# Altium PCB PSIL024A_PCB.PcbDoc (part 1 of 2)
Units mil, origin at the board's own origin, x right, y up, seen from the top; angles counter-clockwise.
Board outline 5700 x 3550 mil, 4 copper layers (Top Layer, MidLayer1, MidLayer2, Bottom Layer), stack 61.2 mil thick; 205 components, 107 nets, 481 pads, 240 vias.
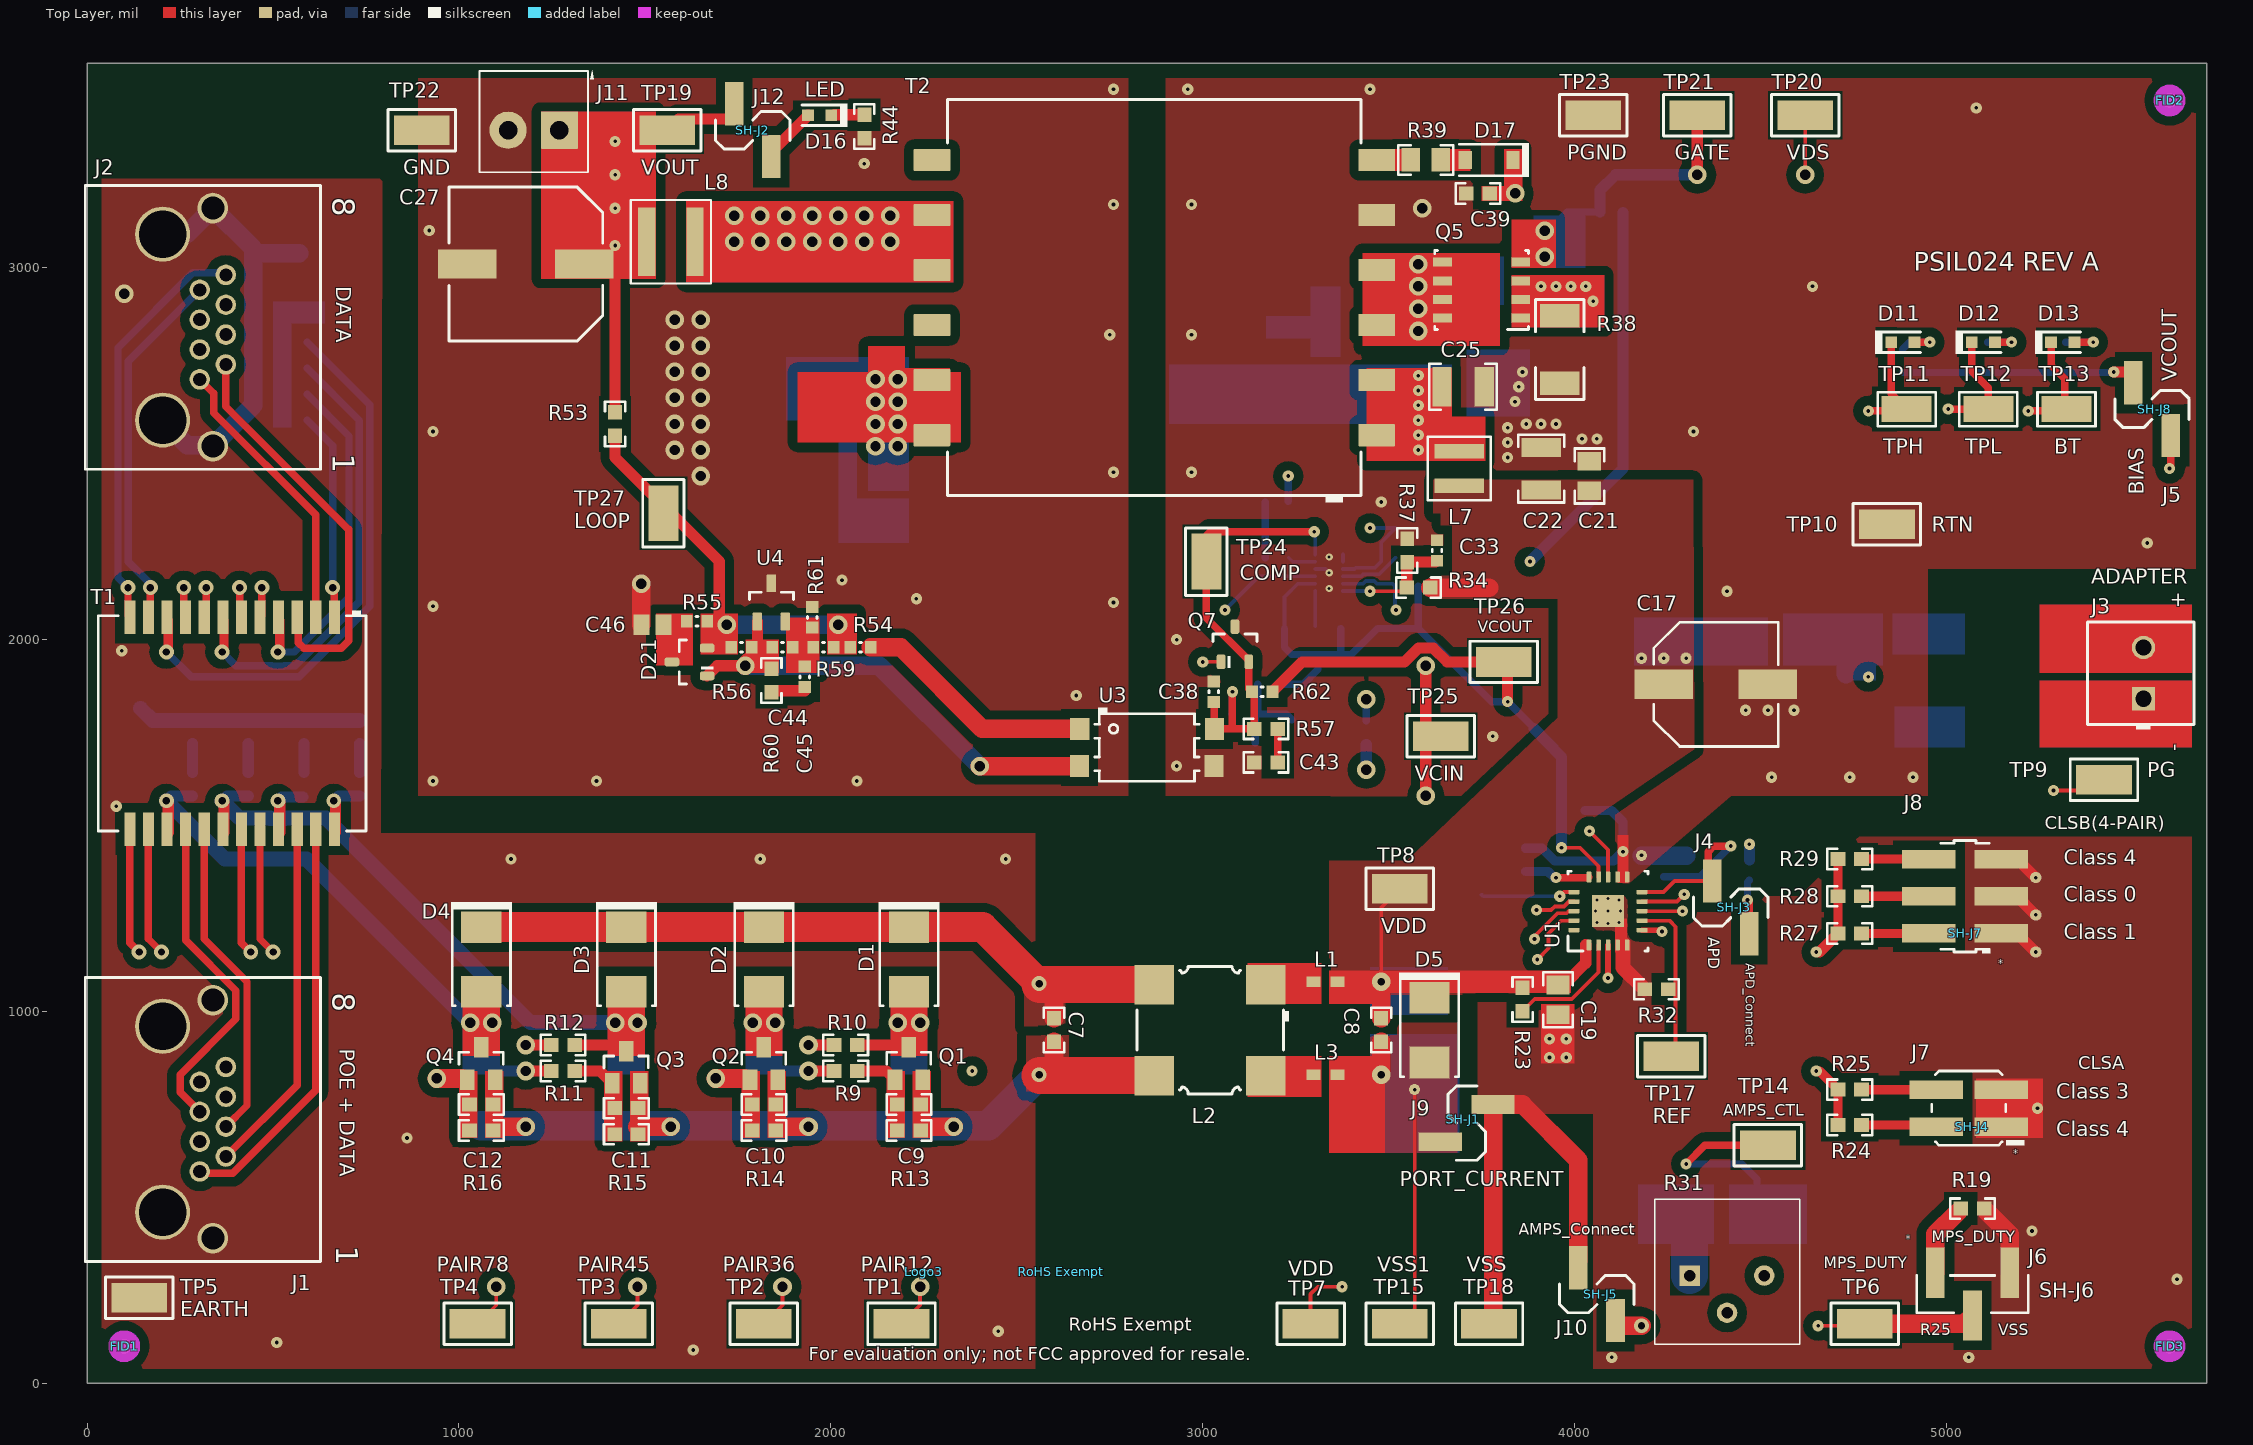
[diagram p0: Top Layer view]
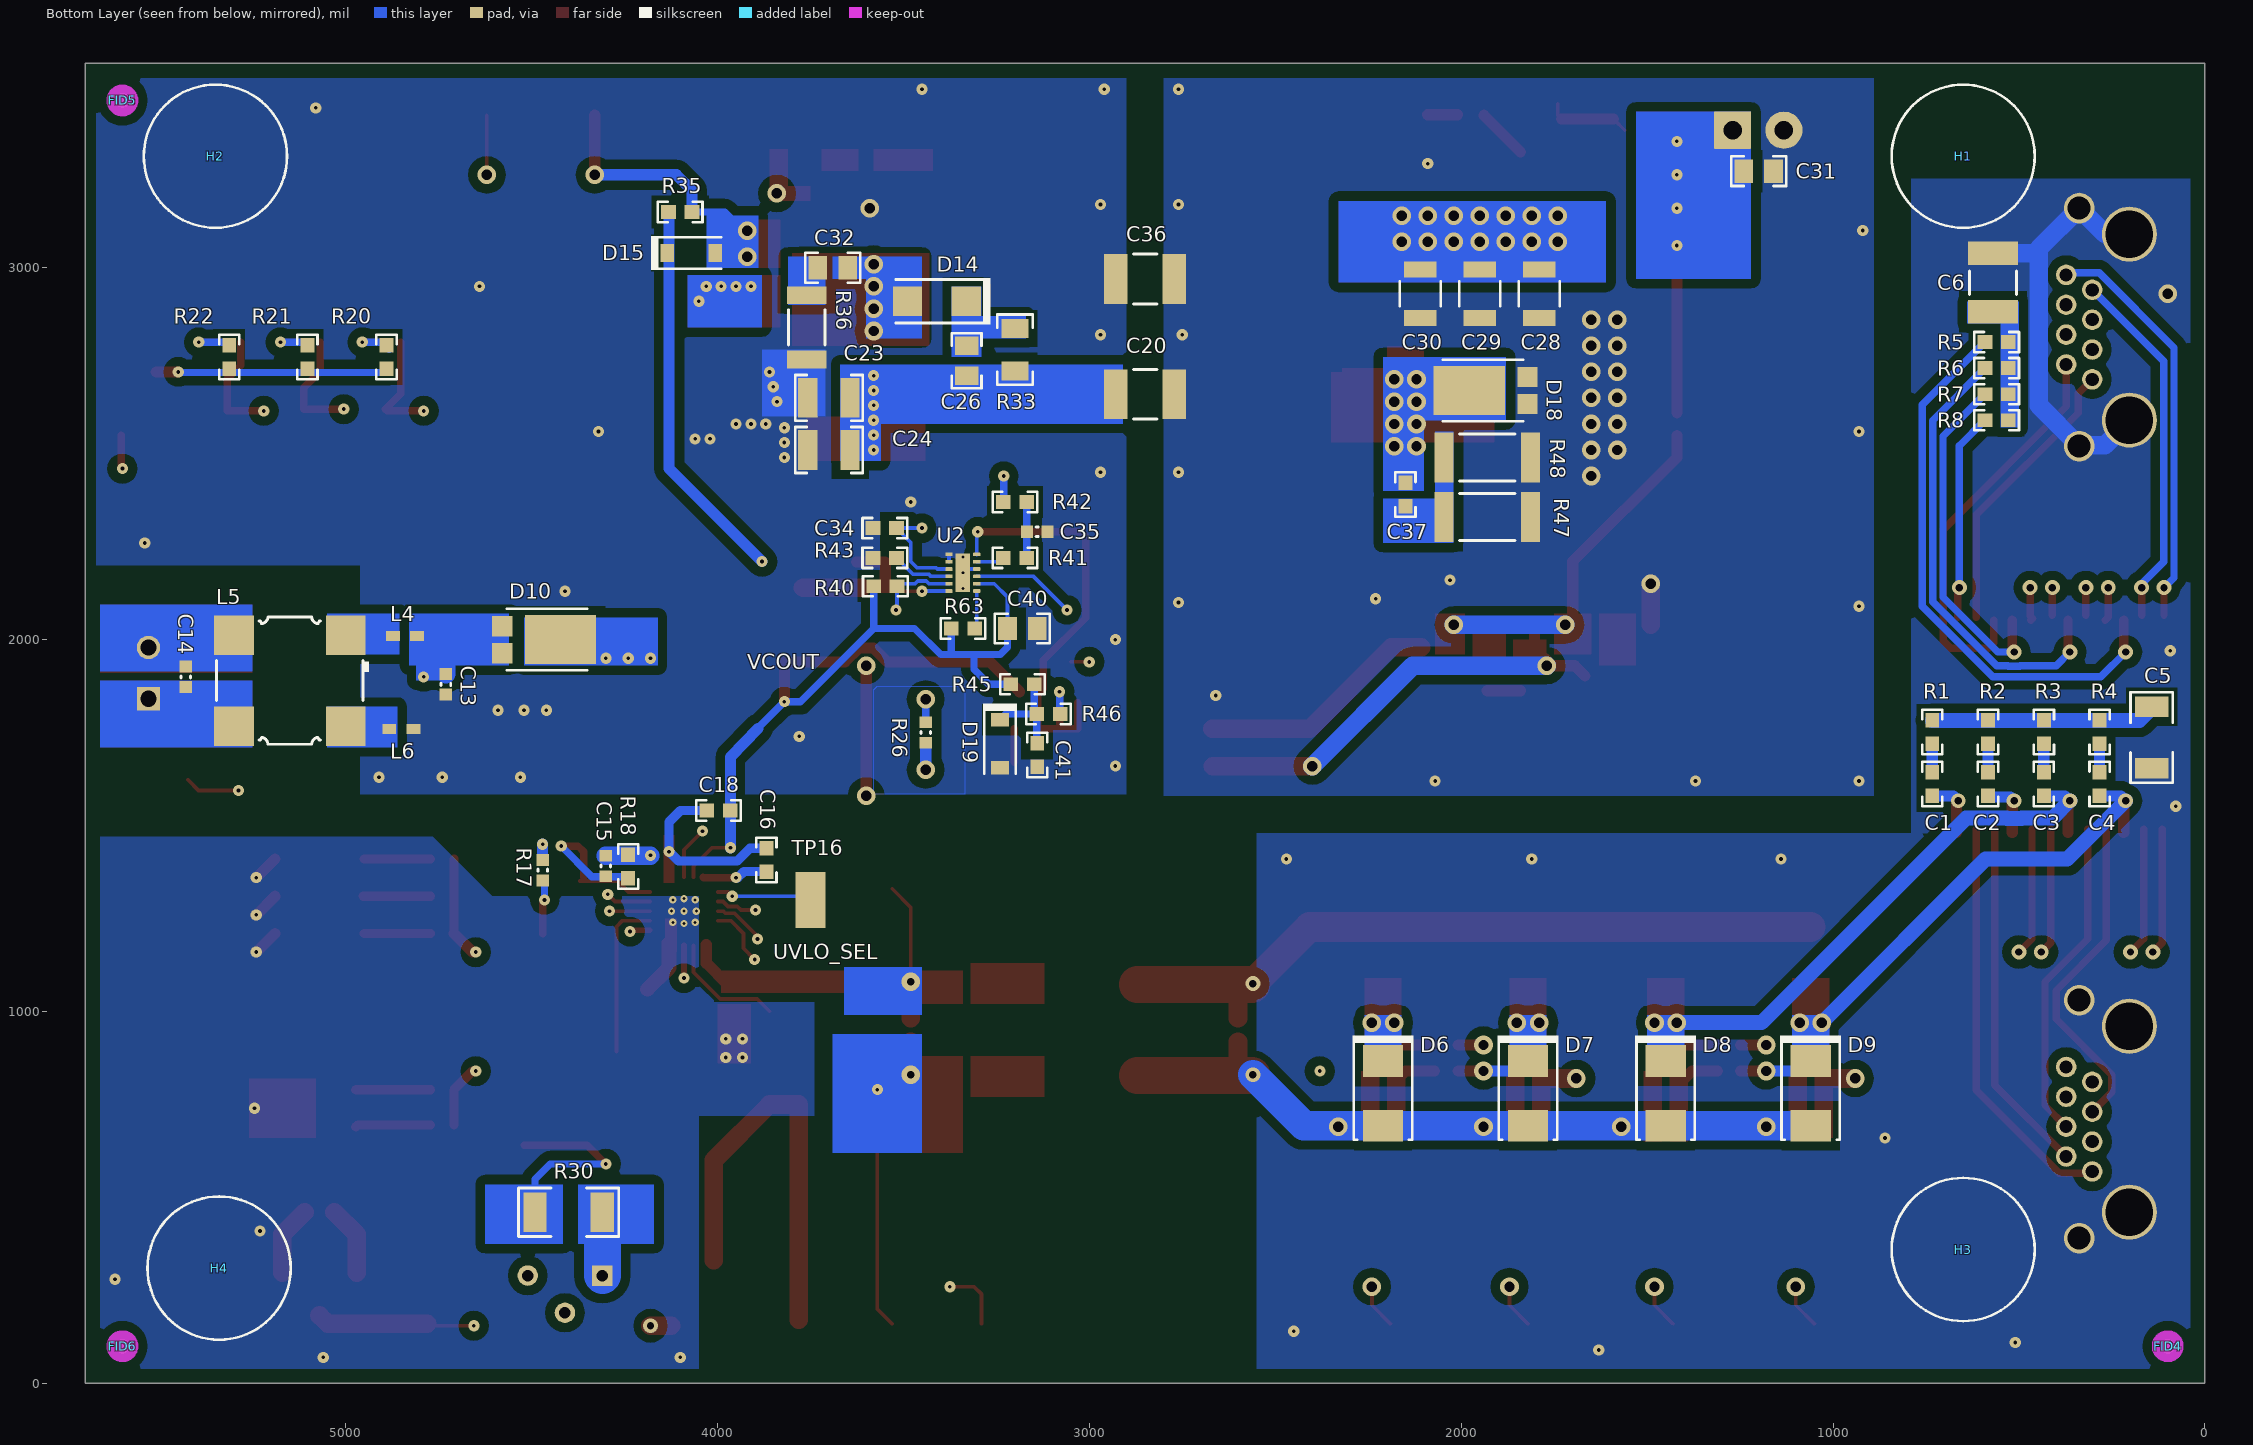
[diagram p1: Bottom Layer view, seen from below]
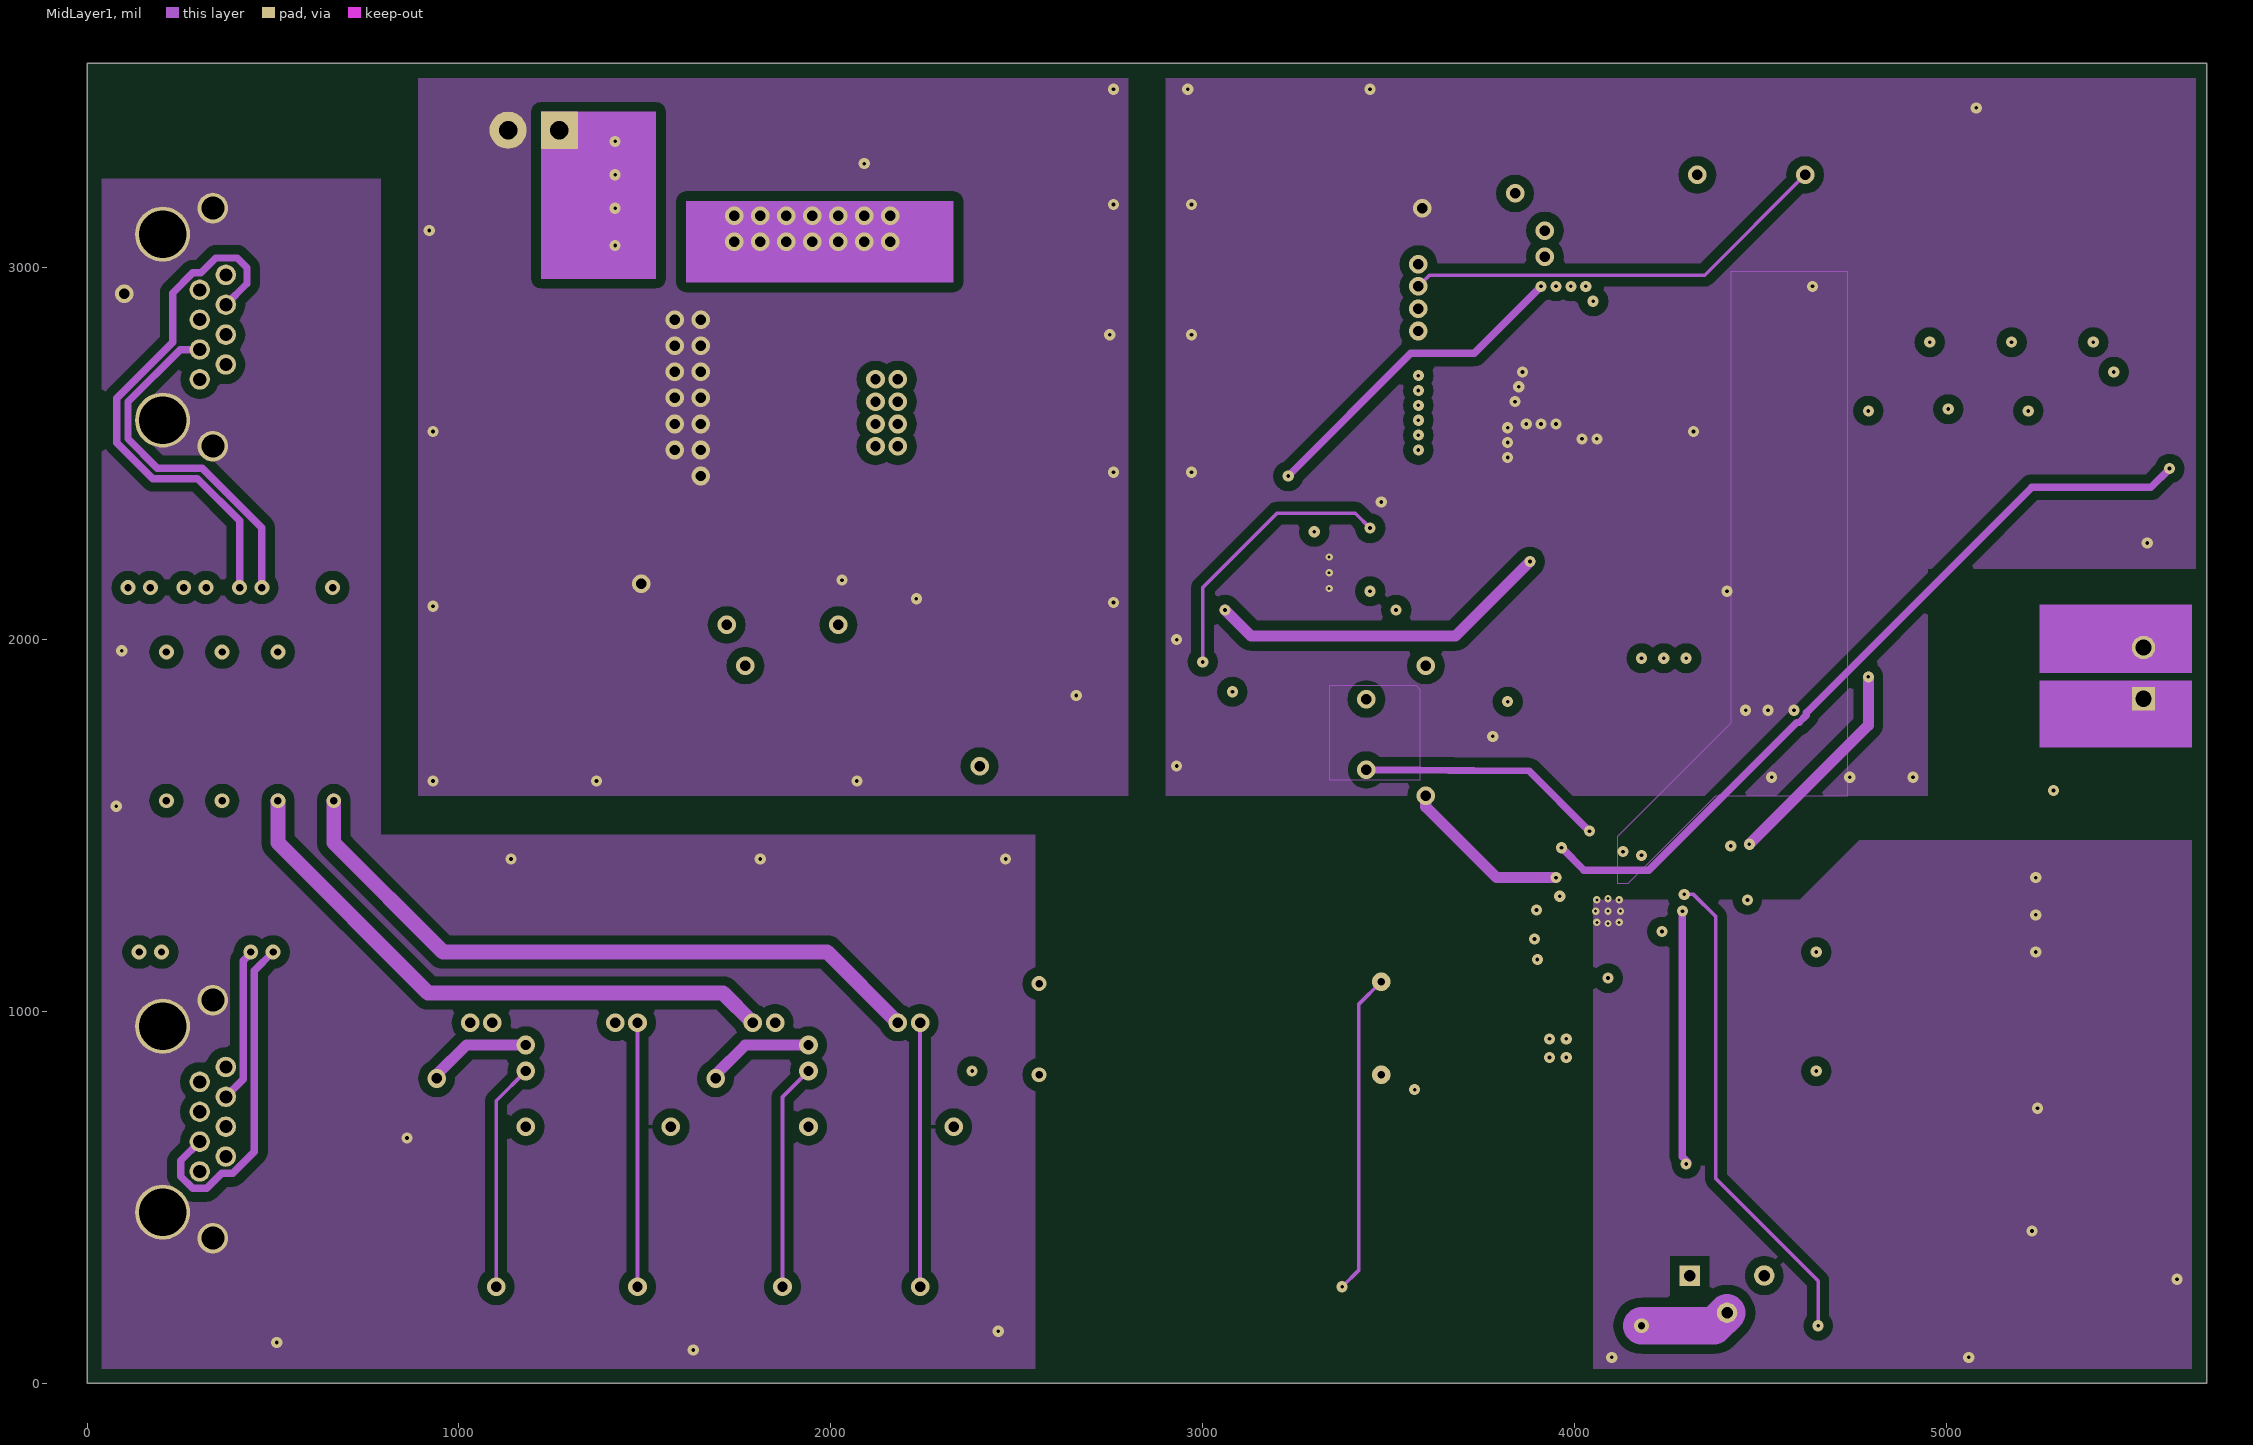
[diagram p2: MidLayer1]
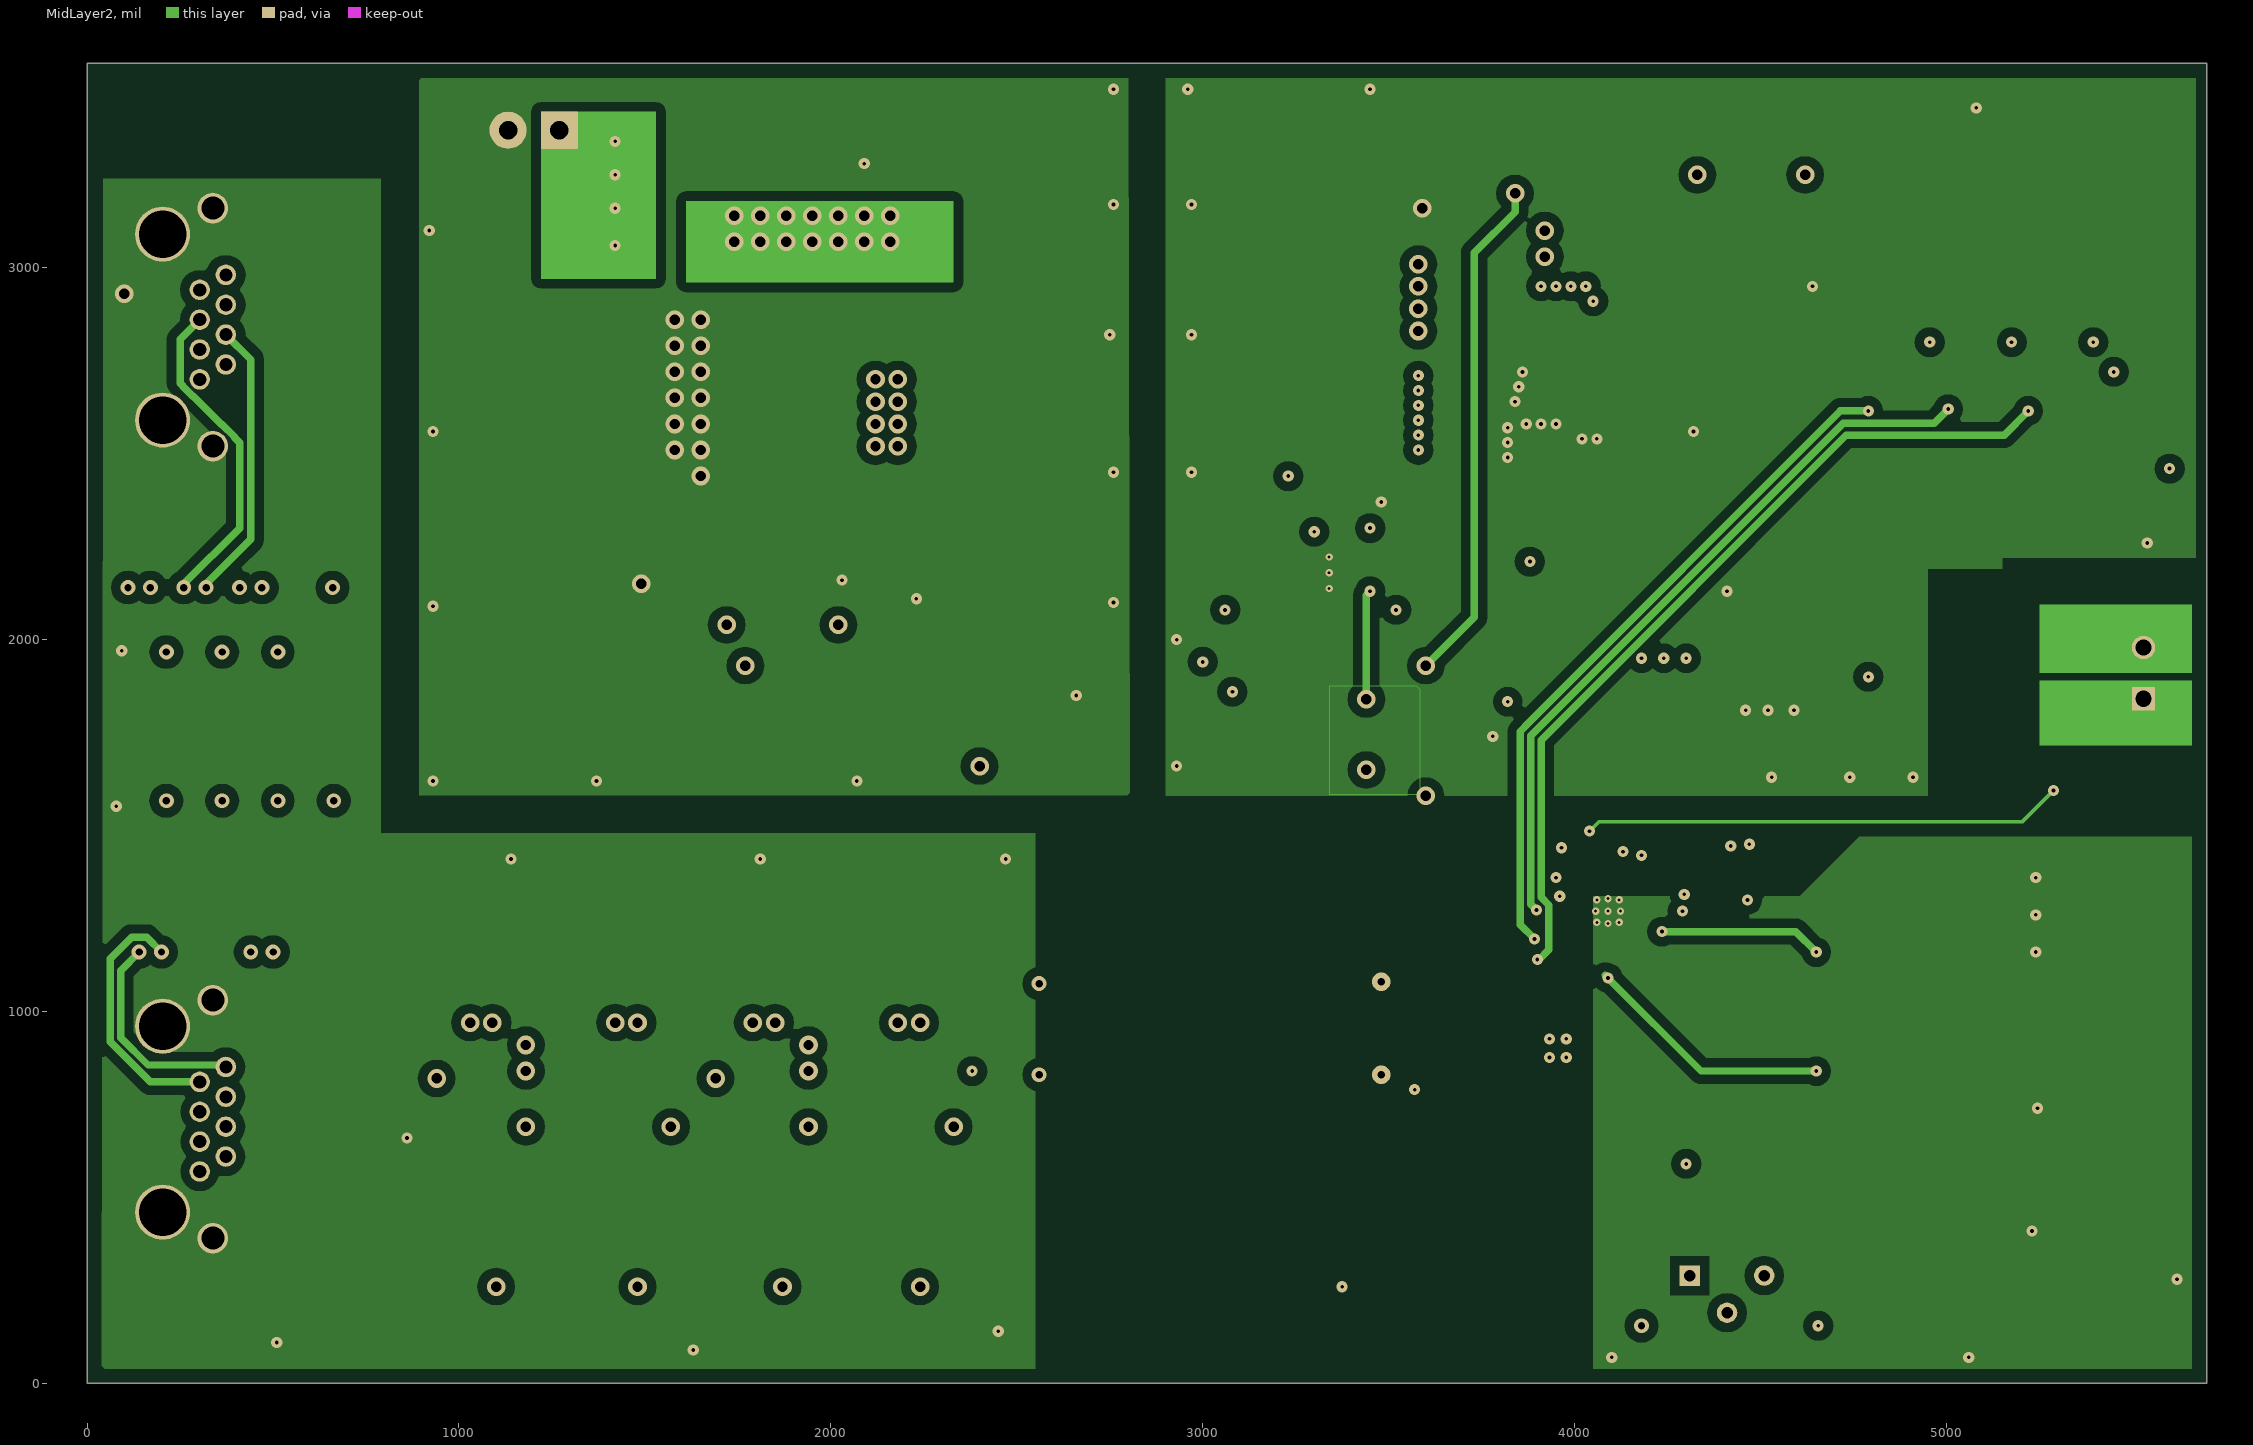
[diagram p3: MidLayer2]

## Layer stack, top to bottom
Top Solder: solder mask 0.4, Solder Resist, Dk 3.5
Top Layer: signal copper 2.8
Dielectric1: core 14.2, FR-4, Dk 4.8
MidLayer1: signal copper 2.8
Dielectric2: prepreg 21.6, FR-4, Dk 4.8
MidLayer2: signal copper 2.8
Dielectric3: core 14.2, FR-4, Dk 4.8
Bottom Layer: signal copper 2.8
Bottom Solder: solder mask 0.4, Solder Resist, Dk 3.5

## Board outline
0,0 5700,0 5700,3550 0,3550

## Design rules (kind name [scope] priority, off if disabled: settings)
AcuteAngle [All] p1: minimum=4.50000000000000E+0001 checktracksonly=TRUE
AssemblyTestPointUsage [All] p1: valid=2
BoardOutlineClearance BoardOutlineClearance_MountingHoles [OnCopper and InComponentClass('Mounting Holes')] p1: gap=40
BoardOutlineClearance BoardOutlineClearance_Poly [OnCopper and InPoly] p2: gap=25
BoardOutlineClearance [OnCopper and Not InComponentClass('Logo') and not InComponentClass('FiducialMark') and not InRegion(1000,500,4000,800)] p3: gap=20
Clearance Clearance_Keepouts [((IsTrack Or IsArc) And Not InPoly) And IsFree and IsKeepOut vs ((IsTrack Or IsArc) And Not InPoly) And IsFree and IsKeepOut] p1: gap=0
Clearance Clearance_Poly [InPolygon] p2: gap=25
Clearance [All] p3: gap=7.87
ComponentClearance ComponentClearance_MountingHoles_FiducialMarks [InComponentClass('Mounting Holes') vs InComponentClass('FiducialMark')] p1: gap=50 collisioncheckmode=3 verticalgap=10 showdistances=FALSE
ComponentClearance ComponentClearance_Shunt [InComponentClass('Header') vs InComponentClass('Shunt')] p2: gap=0 collisioncheckmode=3 verticalgap=0 showdistances=FALSE
ComponentClearance ComponentClearance_Logo [InComponentClass('Logo')] p3: gap=50 collisioncheckmode=3 verticalgap=10 showdistances=FALSE
ComponentClearance ComponentClearance_ScrewToNut [(HasFootprint('NY PMS 440 0025 PH')) vs (HasFootprint('Keystone_1902C'))] p4: gap=5 collisioncheckmode=3 verticalgap=10 showdistances=FALSE
ComponentClearance ComponentClearance_MountingHoles [InComponentClass('Mounting Holes')] p5: gap=250 collisioncheckmode=3 verticalgap=100000 showdistances=FALSE
ComponentClearance ComponentClearance_SmallPassives [HasFootprint('0201*') or HasFootprint('0402*') or HasFootprint('0508') or HasFootprint('0603*') or HasFootprint('0612') or HasFootprint('0805*') or HasFootprint('0815*') or HasFootprint('0830*') or HasFootprint('1206*') or HasFootprint('1210*') or HasFootprint('1808*') or HasFootprint('1812*') or HasFootprint('1825*') or HasFootprint('2010*') or HasFootprint('2220*') or HasFootprint('2225*') or HasFootprint('2512*') or HasFootprint('2728*') or HasFootprint('3518*') vs HasFootprint('0201*') or HasFootprint('0402*') or HasFootprint('0508') or HasFootprint('0603*') or HasFootprint('0612') or HasFootprint('0805*') or HasFootprint('0815*') or HasFootprint('0830*') or HasFootprint('1206*') or HasFootprint('1210*') or HasFootprint('1808*') or HasFootprint('1812*') or HasFootprint('1825*') or HasFootprint('2010*') or HasFootprint('2220*') or HasFootprint('2225*') or HasFootprint('2512*') or HasFootprint('2728*') or HasFootprint('3518*')] p6: gap=14.96 collisioncheckmode=3 verticalgap=10 showdistances=FALSE
ComponentClearance ComponentClearance_THtoSMT [IsThruComponent vs IsSMTComponent] p7: gap=40 collisioncheckmode=3 verticalgap=30 showdistances=FALSE
ComponentClearance ComponentClearance_THtoTH [IsThruComponent vs IsThruComponent] p8: gap=30 collisioncheckmode=3 verticalgap=30 showdistances=FALSE
ComponentClearance [All] p9: gap=30 collisioncheckmode=3 verticalgap=10 showdistances=FALSE
DiffPairsRouting [All] p1: maxlimit=100 minlimit=10 mostfreqgap=10 toplayer_minwidth=15 toplayer_maxwidth=15 toplayer_prefwidth=15 midlayer1_minwidth=15 midlayer1_maxwidth=15 midlayer1_prefwidth=15 midlayer2_minwidth=15 midlayer2_maxwidth=15 midlayer2_prefwidth=15 bottomlayer_minwidth=15 bottomlayer_maxwidth=15 bottomlayer_prefwidth=15 maxuncoupledlength=1000
FabricationTestPointUsage TestPointUsage [All] p1: valid=2 allowmultiple=FALSE
FabricationTestpoint Testpoint [All] p1: side=3 testpointundercomponent=TRUE minsize=40 maxsize=100 preferedsize=60 minholesize=0 maxholesize=40 preferedholesize=32 testpointgrid=1 allowsidetop=TRUE allowsidebottom=TRUE usegrid=TRUE gridtolerance=0.01
FanoutControl Fanout_LCC [IsLCC] p1: bgadir=Out bgaviamode=Centered fanoutstyle=Auto fanoutdirection=Alternating viagrid=1 // Fanout_LCC (Default Rule)
FanoutControl Fanout_BGA [IsBGA] p2: bgadir=Out bgaviamode=Centered fanoutstyle=Auto fanoutdirection=Alternating viagrid=1 // Fanout_BGA (Default Rule)
FanoutControl Fanout_Default [All] p4: bgadir=Out bgaviamode=Centered fanoutstyle=Auto fanoutdirection=Alternating viagrid=1 // Fanout_Default (Default Rule)
FanoutControl Fanout_Small [(CompPinCount < 5)] p5: bgadir=Out bgaviamode=Centered fanoutstyle=Auto fanoutdirection=OutThenIn viagrid=1 // Fanout_Small (Default Rule)
HoleSize [All] p1: absolutevalues=TRUE maxlimit=251 minlimit=7.87 maxpercent=80.000 minpercent=20.000
MinimumAnnularRing MinimumAnnularRing_ThermalPadVias [IsVia and InAnyComponent] p1: minimumring=5.91
MinimumAnnularRing [All] p2: minimumring=5
MinimumSolderMaskSliver MinimumSolderMaskSliver_Logo [InComponentClass('Logo') vs InComponentClass('Logo')] p1: minsoldermaskwidth=0.7
MinimumSolderMaskSliver [All] p2: minsoldermaskwidth=3.94
PlaneConnect [All] p1: planeconnectstyle=Direct reliefexpansion=10 reliefentries=4 reliefconductorwidth=10 reliefairgap=10
PolygonConnect [All] p1: connectstyle=Direct reliefconductorwidth=10 reliefentries=4 polygonreliefangle="90 Angle" airgapwidth=10
RoutingVias ThermalPadVias [IsVia and InAnyComponent] p1: holewidth=7.87 width=19.68 viastyle="Through Hole" minholewidth=7.87 minwidth=19.68 maxholewidth=12.99 maxwidth=23.62
RoutingVias [All] p2: holewidth=16 width=34 viastyle="Through Hole" minholewidth=7.87 minwidth=20 maxholewidth=40 maxwidth=65
SilkToBoardRegionClearance [Not ((IsComment or IsDesignator) And (Hide <> 'False')) and not InRegion(1000,500,4000,800)] p1:
SilkToSilkClearance SilkToSilkClearance_Pb-FreeLogo [(HasFootprint('Pb-Free_Overlay_Medium') OR HasFootprint('Pb-Free_Overlay_Small')) vs (HasFootprint('Pb-Free_Overlay_Medium') OR HasFootprint('Pb-Free_Overlay_Small'))] p1: silktosilkclearance=0
SilkToSilkClearance [All] p2: silktosilkclearance=4
SilkToSolderMaskClearance SilkToComponentPadClearance [IsPad and InAnycomponent] p1: minsilkscreentomaskgap=5 clearancetoexposedcopper=TRUE
SilkToSolderMaskClearance "Silk to Solder Mask Opening" [All] p2: minsilkscreentomaskgap=4 clearancetoexposedcopper=FALSE
SolderMaskExpansion [All] p1: expansion=1.97
Width [All] p1: maxlimit=100 minlimit=6 preferedwidth=10 checkconnectedcopper=TRUE
15 further rules are at their usual default settings.

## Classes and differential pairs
component class PSIL024A_sch2: C13 C14 C15 C16 C17 C18 C19 D10 D11 D12 D13 J3 J4 J5 J6 J7 J8 J9 J10 L4 L5 L6 R17 R18 R19 R20 R21 R22 R23 R24 R25 R26 R27 R28 R29 R30 R31 R32 TP6 TP7 TP8 TP9 TP10 TP11 TP12 TP13 TP14 TP15 TP16 TP17 TP18 U1
component class Shunt: SH-J1 SH-J2 SH-J3 SH-J4 SH-J5 SH-J6 SH-J7 SH-J8
component class PSIL024A_sch3: C20 C21 C22 C23 C24 C25 C26 C27 C28 C29 C30 C31 C32 C33 C34 C35 C36 C37 C38 C39 C40 C41 C43 C44 C45 C46 D14 D15 D16 D17 D18 D19 D21 J11 J12 L7 L8 L? Q5 Q7 R33 R34 R35 R36 R37 R38 R39 R40 R41 R42 R43 R44 R45 R46 R47 R48 R53 R54 R55 R56 R57 R59 R60 R61 R62 R63 T2 TP19 TP20 TP21 TP22 TP23 TP24 TP25 TP26 TP27 U2 U3 U4
component class PSIL024A_sch1: C1 C2 C3 C4 C5 C6 C7 C8 C9 C10 C11 C12 D1 D2 D3 D4 D5 D6 D7 D8 D9 J1 J2 L1 L2 L3 Q1 Q2 Q3 Q4 R1 R2 R3 R4 R5 R6 R7 R8 R9 R10 R11 R12 R13 R14 R15 R16 T1 TP1 TP2 TP3 TP4 TP5
component class Header: J4 J5 J6 J7 J8 J9 J10 J12
component class AssemblyNote: ZZ1 ZZ2 ZZ3
component class FiducialMark: FID1 FID2 FID3 FID4 FID5 FID6
component class PSIL024A_EVM_Hardware: FID1 FID2 FID3 FID4 FID5 FID6 H1 H2 H3 H4 Logo3 "RoHS Exempt" SH-J1 SH-J2 SH-J3 SH-J4 SH-J5 SH-J6 SH-J7 SH-J8 ZZ1 ZZ2 ZZ3

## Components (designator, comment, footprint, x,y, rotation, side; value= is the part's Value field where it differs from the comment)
C1 "C1608X7R2A103K" 0603 733.15,1611.5 r90 bottom
C2 "C1608X7R2A103K" 0603 583.15,1611.5 r90 bottom
C3 "C1608X7R2A103K" 0603 433.15,1611.5 r90 bottom
C4 "C1608X7R2A103K" 0603 283.15,1611.5 r90 bottom
C5 "GR442QR73D102KW01L" 1808 143.15,1736.85 r270 bottom
C6 "1812GC102KAT1A" 1812_220 570,2960 r90 bottom
C7 "C1608X7R2A102K" 0603 2600,950 r270 top
C8 "C1608X7R2A102K" 0603 3480,950 r270 top
C9 "885012006060" 0603 2210,750 r0 top
C10 "885012006060" 0603 1820,750 r0 top
C11 "885012006060" 0603 1450,740 r0 top
C12 "885012006060" 0603 1060,750 r0 top
C13 "C1608X7R2A102K" 0603L 4730,1880 r270 bottom
C14 "C1608X7R2A102K" 0603L 5430,1900 r270 bottom
C15 "C1608X7R1H103K" 0603L 4300,1391.3 r270 bottom
C16 "GRM188R61H103KA01D" 0603 3868.25,1407.75 r90 bottom
C17 "EEE-FK1J470P" SM_RADIAL_F 4380,1880 r0 top
C18 "06033D104KAT2A" 0603 3996.75,1540.5 r0 bottom
C19 "C0805C104K1RACTU" 0805_HV 3955.5,1031.25 r270 top
C20 "1812GC472KAT1A" 1812_254 2850,2660 r0 bottom
C21 "C2012X7R2A104K125AA" 0805_HV 4040,2440 r270 top
C22 "GRM32ER72A225KA35L" 1210_270 3910,2460 r90 top
C23 "GRM32ER72A225KA35L" 1210_270 3700,2650 r0 bottom
C24 "GRM32ER72A225KA35L" 1210_270 3700,2510 r0 bottom
C25 "GRM32ER72A225KA35L" 1210_270 3700,2680 r0 top
C26 "C2012X7R2A104K125AA" 0805_HV 3330,2750 r270 bottom
C27 "PCV1E271MCL1GS" PCV_1000x1270 1180,3010 r180 top
C28 "C1210C106K3RACTU" 1210_280 1790,2930 r270 bottom
C29 "C1210C106K3RACTU" 1210_280 2110,2930 r270 bottom
C30 "C1210C106K3RACTU" 1210_280 1950,2930 r270 bottom
C31 "GRM21BR71E105KA99L" 0805_HV 1200,3260 r180 bottom
C32 "GRM21A5C2E101JW01D" 0805_HV 3690,3000 r0 bottom
C33 "C0603C221J5GACTU" 0603L 3630,2240 r90 top
C34 "C0603C223K3RACTU" 0603 3550,2300 r0 bottom
C35 "GRM1885C1H101JA01D" 0603L 3140,2290 r180 bottom
C36 "1812GC472KAT1A" 1812_254 2850,2970 r0 bottom
C37 "001" 0603 2150,2390 r270 bottom
C38 "GRM1885C1H392JA01D" 0603L 3030,1860 r90 top
C39 "06033C104JAT2A" 0603 3740,3200 r180 top
C40 "GRM21BR71E105KA99L" 0805_HV 3180,2030 r180 bottom
C41 "EMK107BB7225KA-T" 0603 3140,1690 r270 bottom
C43 "06033C473JAT2A" 0603 3170,1670 r180 top
C44 "GRM1885C1H101JA01D" 0603L 1870,1980 r180 top
C45 "C1608X7R1H473K080AA" 0603L 1930,1900 r270 top
C46 "GRM21BR71E105KA99L" 0805L 1520,2040 r180 top
D1 "B2100-13-F" SMB 2210,1140 r270 top
D2 "B2100-13-F" SMB 1820,1140 r270 top
D3 "B2100-13-F" SMB 1450,1140 r270 top
D4 "B2100-13-F" SMB 1060,1140 r270 top
D5 "SMBJ58A-13-F" SMB 3610,950 r270 top
D6 "DNP" SMB 2210,780 r270 bottom
D7 "DNP" SMB 1820,780 r270 bottom
D8 "DNP" SMB 1450,780 r270 bottom
D9 "DNP" SMB 1060,780 r270 bottom
D10 "100V" PowerDI5 4500,2000 r180 bottom
D11 "Yellow" WL-SMCW_YELLOW 4882.8,2799.98 r0 top
D12 "Yellow" WL-SMCW_YELLOW 5099.36,2799.98 r0 top
D13 "Yellow" WL-SMCW_YELLOW 5312.8,2799.98 r0 top
D14 "ES2DA-13-F" SMA 3410,2910 r0 bottom
D15 "MMSD4148T1G" SOD-123 4070,3040 r180 bottom
D16 "150060YS75000" WL-SMCW_YELLOW 1970,3410 r180 top
D17 "MMSD4148T1G" SOD-123 3770,3290 r180 top
D18 "001" PowerDI5 1900,2670 r0 bottom
D19 "MMSZ5231B-7-F" SOD-123 3240,1720 r270 bottom
D21 "BAT54S-7-F" SOT-23 1620,1940 r180 top
FID1 "Fiducial" Fiducial10-20 100,100 r0 top
FID2 "Fiducial" Fiducial10-20 5600,3450 r0 top
FID3 "Fiducial" Fiducial10-20 5600,100 r0 top
FID4 "Fiducial" Fiducial10-20 100,100 r180 bottom
FID5 "Fiducial" Fiducial10-20 5600,3450 r180 bottom
FID6 "Fiducial" Fiducial10-20 5600,100 r180 bottom
H1 "SJ61A2" Bumpon_SJ61A2 650,3300 r180 bottom locked
H2 "SJ61A2" Bumpon_SJ61A2 5350,3300 r180 bottom locked
H3 "SJ61A2" Bumpon_SJ61A2 650,360 r180 bottom locked
H4 "SJ61A2" Bumpon_SJ61A2 5340,310 r180 bottom locked
J1 "1-406541-1" TEC_1-406541-1 310,710 r270 top
J2 "1-406541-1" TEC_1-406541-1 310,2840 r270 top
J3 "39357-0002" Molex_39357-0002 5530,1910 r90 top
J4 "87898-0204" Molex_87898-0204 4420,1280 r180 top
J5 "87898-0204" Molex_87898-0204 5552.8,2620 r180 top
J6 "TSM-103-01-L-SV" Samtec_TSM-103-01-X-SV 5070,240 r0 top
J7 "15-91-2040" Molex_15-91-2040 5060,740 r90 top
J8 "TSM-103-01-L-DV" Samtec_TSM-103-01-x-DV 5050,1310 r180 top
J9 "Port Current" Molex_87898-0204 3710,700 r270 top
J10 "AMPS_Connect" Molex_87898-0204 4060,240 r0 top
J11 "ED555/2DS" TERM_BLK_ED555-2DS 1270,3370 r180 top
J12 "LED" Molex_87898-0204 1790,3370 r0 top
L1 "" WE-CBF_0603 3330,1080 r0 top
L2 "744272251" WE-SL5 3020,950 r270 top
L3 "" WE-CBF_0603 3330,830 r0 top
L4 "" WE-CBF_0603 4840,2010 r180 bottom
L5 "744272251" WE-SL5 5150,1890 r270 bottom
L6 "" WE-CBF_0603 4850,1760 r180 bottom
L7 "XFL4020-332MEB" XFL4020 3690,2460 r90 top
L8 "XAL5030-161MEB" XAL5030 1570,3070 r180 top
Logo3 "FCC disclaimer" FCC_disclaimer 2250,300 r0 top
Q1 "FDN8601" SSOT-3 2210,860 r0 top
Q2 "FDN8601" SSOT-3 1820,860 r0 top
Q3 "FDN8601" SSOT-3 1450,850 r0 top
Q4 "FDN8601" SSOT-3 1060,860 r0 top
Q5 "FDMS86252" TRANS_Fairchild_PQFN08A 3750,2940 r180 top
Q7 "FMMT718TA" SOT-23 3086.69,1987.71 r90 top
R1 "CRCW060375R0FKEA" 0603 733.15,1751.5 r270 bottom
R2 "CRCW060375R0FKEA" 0603 583.15,1751.5 r270 bottom
R3 "CRCW060375R0FKEA" 0603 433.15,1751.5 r270 bottom
R4 "CRCW060375R0FKEA" 0603 283.15,1751.5 r270 bottom
R5 "CRCW060375R0FKEA" 0603 560,2800 r180 bottom
R6 "CRCW060375R0FKEA" 0603 560,2730 r180 bottom
R7 "CRCW060375R0FKEA" 0603 560,2660 r180 bottom
R8 "CRCW060375R0FKEA" 0603 560,2590 r180 bottom
R9 "CRCW06031M00FKEA" 0603 2040,840 r180 top
R10 "CRCW06031M00FKEA" 0603 2040,910 r0 top
R11 "CRCW06031M00FKEA" 0603 1280,840 r180 top
R12 "CRCW06031M00FKEA" 0603 1280,910 r0 top
R13 "CRCW0603232KFKEA" 0603 2210,680 r180 top
R14 "CRCW0603232KFKEA" 0603 1820,680 r180 top
R15 "CRCW0603232KFKEA" 0603 1450,670 r180 top
R16 "CRCW0603232KFKEA" 0603 1060,680 r180 top
R17 "CRCW0603237KFKEA" 0603L 4470,1380 r90 bottom
R18 "CRCW06039K53FKEA" 0603 4240,1390 r270 bottom
R19 "CRCW060360K4FKEA" 0603 5070,470 r0 top
R20 "CRCW060324K9FKEA" 0603 4890,2760 r270 bottom
R21 "CRCW060324K9FKEA" 0603 5102.8,2759.98 r270 bottom
R22 "CRCW060324K9FKEA" 0603 5312.8,2759.98 r270 bottom
R23 "RC0603FR-0727K4L" 0603 3860.25,1032.5 r90 top
R24 "CRCW060363R4FKEA" 0603 4740,695 r180 top
R25 "CRCW060390R9FKEA" 0603 4740,790 r180 top
R26 "CRCW06030000Z0EA" 0603L 3440,1750 r90 bottom
R27 "CRCW0603249RFKEA" 0603 4740,1210 r180 top
R28 "CRCW06031K21FKEA" 0603 4740,1310 r180 top
R29 "CRCW060363R4FKEA" 0603 4740,1410 r180 top
R30 "CRCW20101K00FKEF" 2010 4400,460 r0 bottom
R31 "3386P-1-202LF" BOURNS_3386P 4410,300 r0 top
R32 "CRCW060349K9FKEA" 0603 4220,1060 r180 top
R33 "CRCW120639K0JNEA" 1206 3200,2780 r270 bottom
R34 "133k" 0603 3580,2140 r0 top
R35 "CRCW060310R0JNEA" 0603 4100,3150 r180 bottom
R36 "CRCW201075R0JNEF" 2010L 3760,2840 r90 bottom
R37 "RT0603DRE074K99L" 0603 3550,2240 r270 top
R38 "CSRN2010FK20L0" 2010 3960,2780 r90 top
R39 "CRCW08055R23FKEA" 0805_HV 3600,3290 r180 top
R40 "100k" 0603 3548.46,2143.7 r180 bottom
R41 "MCR03EZPJ000" 0603 3200,2220 r180 bottom
R42 "499" 0603 3200,2370 r0 bottom
R43 "71.5k" 0603 3550,2220 r180 bottom
R44 "CRCW06034K42FKEA" 0603 2090,3380 r90 top
R45 "CRCW06032K61FKEA" 0603 3180,1880 r0 bottom
R46 "CRCW06032K32FKEA" 0603 3110,1800 r0 bottom
R47 "001" 2512 1930,2330 r0 bottom
R48 "001" 2512 1930,2490 r0 bottom
R53 "CRCW060350R0FKEA" 0603 1420,2580 r90 top
R54 "CRCW06032K10FKEA" 0603L 2080,1980 r180 top
R55 "CRCW060310K0FKEA" 0603L 1640,2050 r0 top
R56 "CRCW06034K99FKEA" 0603L 1760,1980 r180 top
R57 "CRCW0603887RFKEA" 0603 3170,1760 r180 top
R59 "CRCW060310K0FKEA" 0603L 1980,1980 r0 top
R60 "CRCW060314K7FKEA" 0603 1840,1890 r270 top
R61 "CRCW06032K61FKEA" 0603L 1950,2060 r270 top
R62 "CRCW060310K2FKEA" 0603L 3160,1860 r0 top
R63 "MCR03EZPJ000" 0603 3340,2030 r180 bottom
"RoHS Exempt" "EU RoHS Exempt Logo" EURoHS_Exempt_60mil 2620,300 r90 top
SH-J1 "SPC02SYAN" SPC02SYAN 3700,710 r270 top
SH-J2 "SPC02SYAN" SPC02SYAN 1790,3370 r0 top
SH-J3 "SPC02SYAN" SPC02SYAN 4430,1280 r0 top
SH-J4 "SPC02SYAN" SPC02SYAN 5070,690 r0 top
SH-J5 "SPC02SYAN" SPC02SYAN 4070,240 r0 top
SH-J6 "SPC02SYAN" SPC02SYAN 5000,250 r180 top
SH-J7 "SPC02SYAN" SPC02SYAN 5050,1210 r0 top
SH-J8 "SPC02SYAN" SPC02SYAN 5560,2620 r0 top
T1 "7490220122" Wurth_7490220122 390,1775 r270 top
T2 "750317065" Wurth_EFD25_4476 2870,2920 r180 top
TP1 "TESTPOINT" Keystone_5019 2190,160 r0 top
TP2 "TESTPOINT" Keystone_5019 1820,160 r0 top
TP3 "TESTPOINT" Keystone_5019 1430,160 r0 top
TP4 "TESTPOINT" Keystone_5019 1050,160 r0 top
TP5 "TESTPOINT" Keystone_5019 140,230 r0 top
TP6 "TESTPOINT" Keystone_5019 4780,160 r0 top
TP7 "VDD" Keystone_5019 3290,160 r0 top
TP8 "VDD" Keystone_5019 3530,1330 r0 top
TP9 "PG" Keystone_5019 5423.75,1623 r0 top
TP10 "RTN" Keystone_5019 4840,2310 r0 top
TP11 "5015" Testpoint_Keystone_Miniature 4892.8,2619.98 r0 top
TP12 "5015" Testpoint_Keystone_Miniature 5112.8,2619.98 r0 top
TP13 "5015" Testpoint_Keystone_Miniature 5322.8,2619.98 r0 top
TP14 "AMPS_CTL" Keystone_5019 4520,640 r0 top
TP15 "VSS1" Keystone_5019 3530,160 r0 top
TP16 "UVLO_SEL" Keystone_5019 3750,1300 r90 bottom
TP17 "REF" Keystone_5019 4260,880 r180 top
TP18 "VSS" Keystone_5019 3770,160 r0 top
TP19 "VOUT" Keystone_5019 1560,3370 r0 top
TP20 "TESTPOINT" Keystone_5019 4620,3410 r0 top
TP21 "TESTPOINT" Keystone_5019 4330,3410 r0 top
TP22 "TESTPOINT" Keystone_5019 900,3370 r180 top
TP23 "TESTPOINT" Keystone_5019 4050,3410 r0 top
TP24 "COMP" Keystone_5019 3010,2210 r90 top
TP25 "TESTPOINT" Keystone_5019 3640,1740 r0 top
TP26 "VCOUT" Keystone_5019 3810,1940 r0 top
TP27 "TESTPOINT" Keystone_5019 1550,2340 r90 top
U1 "TPS2373-3RGWR" RGW0020B 4090,1270 r90 top
U2 "LM51551QDSSRQ1" DSS0012C 3340,2180 r0 bottom
U3 "FOD817AS" N04C 2850,1710 r0 top
U4 "TL431LIAIDBZR" DBZ0003A_M 1840,2100 r90 top
ZZ1 "These assemblies are ESD sensitive, ESD precautions shall be observed." AssemblyNote 115,4529.11 r0 top
ZZ2 "These assemblies must be clean and free from flux and all contaminants. Use of no clean flux is not acceptable." AssemblyNote 115,4440.56 r0 top
ZZ3 "These assemblies must comply with workmanship standards IPC-A-610 Class 2, unless otherwise specified." AssemblyNote 115,4352 r0 top

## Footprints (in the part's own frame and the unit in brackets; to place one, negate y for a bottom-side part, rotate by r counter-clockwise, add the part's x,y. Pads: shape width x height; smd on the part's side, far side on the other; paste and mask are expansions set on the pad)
0603 [mm] "0603 from SM-752 data"
  rect 1x0.95 smd: 1(-0.8,0) 2(0.8,0)
  silkscreen extent -1.52,-0.69 1.52,0.69, body extent -0.87,-0.47 0.87,0.47, height 1
0603L [mm] "0603 from SM-752 data"
  rect 0.8x0.85 smd: 1(-0.7,0) 2(0.7,0)
  silkscreen extent -0.07,-0.33 0.07,0.33, body extent -0.87,-0.47 0.87,0.47, height 1
0805_HV [mil] "0805 with 30mil clearance between pads"
  rect 50x63 smd: 1(-40,0) 2(40,0)
  silkscreen extent -74,-40 74,40, body extent -43,-29 43,29, height 57
0805L [mm] "0805 from SM-752 data"
  rect 1.1x1.4 smd: 1(-0.75,0) 2(0.75,0)
  body extent -1.1,-0.72 1.1,0.72, height 1.45
1206 [mm] "1206 from SM-752 data"
  rect 1.3x1.85 smd: 1(-1.45,0) 2(1.45,0)
  silkscreen extent -2.4,-1.21 2.4,1.21, body extent -1.7,-0.9 1.7,0.9, height 1.35
1210_270 [mm] "1210"
  rect 1.3x2.7 smd: 1(-1.45,0) 2(1.45,0)
  silkscreen extent -2.32,-1.57 2.32,1.57, body extent -1.7,-1.35 1.7,1.35, height 2.7
1210_280 [mm] "SMD, 2-Leads, Body 3.6x2.8mm, Height 2.8mm"
  rect 1.1x2.2 smd: 1(-1.65,0) 2(1.65,0)
  silkscreen extent -0.84,-1.4 0.84,1.4, body extent -1.8,-1.4 1.8,1.4, height 2.8
1808 [mm] "Chip Capacitor, Body 4.6x2.0mm, IPC Medium Density"
  rect 1.4x2.3 smd: 1(-2.1,0) 2(2.1,0)
  silkscreen extent -3.1,-1.45 3.1,1.45, body extent -2.47,-1.2 2.47,1.2, height 2.03
1812_220 [mm] "1812"
  rect 1.6x3.4 smd: 1(-2,0) 2(2,0)
  silkscreen extent -0.8,-1.6 0.8,1.6, body extent -2.4,-1.7 2.4,1.7, height 2.2
1812_254 [mm] "SMD, 2-Leads, Body 4.8x3.4mm"
  rect 1.6x3.4 smd: 1(-2,0) 2(2,0)
  silkscreen extent -0.8,-1.7 0.8,1.7, body extent -2.4,-1.7 2.4,1.7, height 2.54
2010 [mm] "Chip Capacitor, Body 5.08x2.54mm, IPC Medium Density"
  rect 1.6x2.7 smd: 1(-2.3,0) 2(2.3,0)
  silkscreen extent -3.42,-1.65 3.42,1.65, body extent -2.73,-1.45 2.73,1.45, height 1.66
2010L [mm]
  rect 1.2x2.7 smd: 1(-2.2,0) 2(2.2,0)
  silkscreen extent -1.2,-1.25 1.2,1.25, body extent -2.73,-1.45 2.73,1.45, height 1.66
2512 [mm] "Chip Resistor, Body 6.3x3.2mm, IPC Medium Density"
  rect 1.3x3.4 smd: 1(-2.95,0) 2(2.95,0)
  silkscreen extent -1.9,-1.6 1.9,1.6, body extent -3.22,-1.67 3.22,1.67, height 0.71
AssemblyNote [mil] "Assembly Note"
BOURNS_3386P [mil] "BOURND"
  rect 55x55 hole 31: 1(-100,-10)
  round 55 hole 31: 2(0,-110) 3(100,-10)
  silkscreen extent -195,-195 195,195, body extent -193,-192 193,193, height 201
Bumpon_SJ61A2 [mil] "3M Hemispherical Bumpon transparent"
  round 1 on Mech4: 0(0,0)
  silkscreen extent -192,-192 192,192, body extent -193,-192 193,192, height 250
DBZ0003A_M [mm] "SOT23, 3-Leads, Body 2.9x1.3mm, Pitch 0.95mm, Lead Span 2.4mm, IPC Low Density"
  rrect15% 1.2x0.65 smd: 1(-1.3,0.95) 2(-1.3,-0.95) 3(1.3,0)
  silkscreen extent 0.2,-1.5 0.7,1.5, body extent -1.26,-1.46 1.26,1.46, height 0.98
DSS0012C [mm] "WSON-12"
  rrect40% 0.5x0.25 smd: 1(-0.95,1.25) 2(-0.95,0.75) 3(-0.95,0.25) 4(-0.95,-0.25) 5(-0.95,-0.75) 6(-0.95,-1.25) 7(0.95,-1.25) 8(0.95,-0.75) 9(0.95,-0.25) 10(0.95,0.25) 11(0.95,0.75) 12(0.95,1.25)
  rrect11% 0.95x1.17 on Bottom Paste: 13(0,-0.685) 13(0,0.685)
  rrect11% 1x2.65 smd paste-0.5: 13(0,0)
  body extent -1,-1.5 1,1.5, height 0.81
EURoHS_Exempt_60mil [mil] "EU RoHS Exempt symbol"
FCC_disclaimer [mil]
Fiducial10-20 [mm]
  round 1 smd mask+0.5: 1(0,0)
  Top Layer keep-out circle w1.178: c0,0 r0.5
Keystone_5019 [mm] "Test Point, Miniature, SMT"
  rect 3.8x2.03 smd: 1(0,0)
  silkscreen extent -2.31,-1.42 2.31,1.42, body extent -1.9,-1.02 1.9,1.02, height 2.29
Molex_15-91-2040 [mil] "Molex"
  rect 50x144.88 smd: 1(-50,-87.5) 2(-50,87.5) 3(50,-87.5) 4(50,87.5)
  silkscreen extent -100,-150 100,100, body extent -100,-137 100,138, height 380
Molex_39357-0002 [mm] "Terminal Block, 3.5 mm, 2x1, TH"
  rect 1.6x1.6 hole 1.1: 1(-1.75,0)
  round 1.6 hole 1.1: 2(1.75,0)
  silkscreen extent -3.86,-3.45 3.5,3.84, body extent -3.55,-3.45 3.56,3.84, height 8.51
Molex_87898-0204 [mm] "Header, 2.54 mm, 2x1, R/A, SMT"
  rect 1.27x2.96 smd: 1(-1.27,1.8) 2(1.27,-1.8)
  silkscreen extent -2.54,-1.27 2.54,1.27, body extent -2.54,-2.4 2.54,2.4, height 9.65
N04C [mm] "FAIRCHILD"
  rect 1.3x1.5 smd mask+0.065: 1(-4.587,1.27) 2(-4.612,-1.27) 3(4.588,-1.27) 4(4.613,1.27)
  silkscreen extent -3.56,-2.3 3.56,2.72, body extent -5.08,-2.3 5.08,2.3, height 3.87
PCV_1000x1270 [mm] "SMD, 2-Leads, Dia 10mm"
  rect 4x2 smd: 1(-4,0) 2(4,0)
  silkscreen extent -5.25,-5.25 5.25,5.25, body extent -5.25,-5.25 5.25,5.25, height 12.71
PowerDI5 [mm] "Diodes Inc recommended land pattern, ap02001.pdf rev 60"
  rect 1.4x1.39 smd: 1(-1.991,0.92) 2(-1.991,-0.92)
  rect 4.86x3.36 smd: 3(1.991,0)
  silkscreen extent -1.7,-2.1 3.8,2.1, body extent -2.27,-2.02 4.33,2.03, height 1.17
RGW0020B [mm] "QFN, 20-Leads, Body 5x5mm, Pitch 0.65mm, Thermal Pad 2.2x2.2mm, TI Recommended"
  rrect32% 0.75x0.31 smd: 1(-2.325,1.3) 2(-2.325,0.65) 3(-2.325,0) 4(-2.325,-0.65) 5(-2.325,-1.3) 11(2.325,-1.3) 12(2.325,-0.65) 13(2.325,0) 14(2.325,0.65) 15(2.325,1.3)
  rrect32% 0.31x0.75 smd: 6(-1.3,-2.325) 7(-0.65,-2.325) 8(0,-2.325) 9(0.65,-2.325) 10(1.3,-2.325) 16(1.3,2.325) 17(0.65,2.325) 18(0,2.325) 19(-0.65,2.325) 20(-1.3,2.325)
  rrect10% 0.98x0.98 on Top Paste: 21(-0.59,-0.59) 21(-0.59,0.59) 21(0.59,-0.59) 21(0.59,0.59)
  rrect5% 2.2x2.2 smd paste-1.1: 21(0,0)
  silkscreen extent -2.73,-2.73 2.73,2.73, body extent -2.5,-2.5 2.5,2.5, height 0.97
Samtec_TSM-103-01-x-DV [mm] "Header, 2.54mm, 3x2, SMT"
  rect 3.68x1.27 smd: 1(-2.475,2.54) 2(2.475,2.54) 3(-2.475,0) 4(2.475,0) 5(-2.475,-2.54) 6(2.475,-2.54)
  silkscreen extent -1.75,-3.81 1.65,3.9, body extent -3.85,-3.81 3.85,3.81, height 9.65
Samtec_TSM-103-01-X-SV [mil] "Samtec recommended land pattern"
  rect 50x135 smd: 1(-100,57.5) 2(0,-57.5) 3(100,57.5)
  silkscreen extent -150,-50 150,50, body extent -150,-104 150,104, height 381
SM_RADIAL_F [mm] "8 x 10.2mm:  Panasonic F"
  rect 4x2 smd: 1(-3.55,0) 2(3.55,0)
  silkscreen extent -4.25,-4.25 4.25,4.25, body extent -4.25,-4.25 4.25,4.25, height 10.5
SMA [mm] "Molded Diode, 2-Leads, Body 4.3x2.6mm, IPC Medium Density, based on OnSemi component dimensions and land pattern"
  rect 2x2 smd: 1(-2,0) 2(2,0)
  silkscreen extent -3.66,-1.57 2.79,1.57, body extent -2.6,-1.3 2.6,1.3, height 2.42
SMB [mil] "Molded Diode, 2-Leads, Body 5.4x3.6mm, IPC Medium Density, based on OnSemi component dimensions"
  rect 85x107.99 smd: 1(-87.01,0) 2(87.01,0)
  silkscreen extent -155,-82 125,82, body extent -106,-71 106,71, height 91
SOD-123 [mm] "On Semi recommended land pattern"
  rect 0.915x1.22 smd: 1(-1.637,0) 2(1.637,0)
  silkscreen extent -2.74,-1.17 2.03,1.17, body extent -1.93,-0.9 1.93,0.9, height 1.35
SOT-23 [mm] "SOT23, 3-Leads, Body 2.9x1.3mm, Pitch 0.95mm, Lead Span 2.5mm, IPC Medium Density"
  rrect50% 1x0.6 smd: 1(-1.2,0.95) 2(-1.2,-0.95) 3(1.2,0)
  silkscreen extent -1.62,-1.5 0.7,1.5, body extent -1.16,-1.45 1.21,1.45, height 1
SPC02SYAN [mil] "SULLINS"
  round 1 on Mech3: 0(0,0)
  body extent -98,-47 99,47, height 366
SSOT-3 [mm] "SuperSOT-3"
  rect 1x1.4 smd: 1(-0.95,-1.1) 2(0.95,-1.1) 3(0,1.1)
  silkscreen extent -1.53,-0.05 1.5,0.77, body extent -1.52,-0.76 1.52,0.76, height 1.12
TEC_1-406541-1 [mm] "TE Connectivity"
  round 1.4 hole 0.89: 1(3.56,-0.18) 2(2.54,1.6) 3(1.52,-0.18) 4(0.5,1.6) 5(-0.52,-0.18) 6(-1.54,1.6) 7(-2.56,-0.18) 8(-3.58,1.6)
  round 2.1 hole 1.57: 9(8.12,0.71) 10(-8.14,0.71)
  round 3.759 hole 3.251: 11(6.34,-2.72) 12(-6.36,-2.72)
  silkscreen extent -9.69,-8 9.69,8.06, body extent -9.33,-8 9.31,7.75, height 14.8
TERM_BLK_ED555-2DS [mil]
  rrect4% 100x100 hole 50: 1(0,0)
  round 100 hole 50: 2(138,0)
  silkscreen extent -93,-161 215,113, body extent -69,-150 207,106, height 323
Testpoint_Keystone_Miniature [mil] "Miniature SMT test point"
  rect 135x70 smd: 1(0,0)
  silkscreen extent -78,-46 78,45, body extent -52,-20 52,20, height 61
TRANS_Fairchild_PQFN08A [mm] "Fairchild PQFN08A recommended land pattern"
  rect 1.27x0.61 smd: 1(-2.67,1.905) 2(-2.67,0.635) 3(-2.67,-0.635) 4(-2.67,-1.905) 5(2.67,-1.905) 6(2.67,-0.635) 7(2.67,0.635) 8(2.67,1.905)
  Top Layer region: -1.215,-2.55 2.535,-2.55 2.535,2.55 -1.215,2.55
  silkscreen extent -3.2,-2.7 3.2,2.7, body extent -3.05,-2.55 3.05,2.55, height 1.11
WE-CBF_0603 [mm] "WE_SMT-0603"
  rect 0.95x0.7 smd: 1(-0.825,0) 2(0.825,0)
  body extent -0.9,-0.5 0.9,0.5, height 1
WE-SL5 [mm] "SMD, 4-Leads, Body 8.7x10mm"
  rect 2.7x2.7 smd: 1(-3.11,3.81) 2(-3.11,-3.81) 3(3.11,-3.81) 4(3.11,3.81)
  silkscreen extent -4.35,-5 4.35,5.4, body extent -4.35,-5 4.35,5, height 6
WL-SMCW_YELLOW [mm] "WURTH"
  rect 0.8x0.8 smd: 1(-0.8,0) 2(0.8,0)
  silkscreen extent -1.9,-0.8 1.2,0.8, body extent -0.85,-0.45 0.85,0.45, height 0.8
Wurth_7490220122 [mm] "SMD, 24-Leads, Body 14.7x18.29mm"
  rect 2.29x0.76 smd: 1(-7.24,6.985) 2(-7.24,5.715) 3(-7.24,4.445) 4(-7.24,3.175) 5(-7.24,1.905) 6(-7.24,0.635) 7(-7.24,-0.635) 8(-7.24,-1.905) 9(-7.24,-3.175) 10(-7.24,-4.445) 11(-7.24,-5.715) 12(-7.24,-6.985) 13(7.24,-6.985) 14(7.24,-5.715) 15(7.24,-4.445) 16(7.24,-3.175) 17(7.24,-1.905) 18(7.24,-0.635) 19(7.24,0.635) 20(7.24,1.905) 21(7.24,3.175) 22(7.24,4.445) 23(7.24,5.715) 24(7.24,6.985)
  silkscreen extent -7.7,-9.15 7.35,9.15, body extent -7.35,-9.15 7.35,9.15, height 8.81
Wurth_EFD25_4476 [mm] "SMD, 12-Leads, Body 32.45x27.03mm"
  rrect7% 2.5x1.52 smd: 1(-15.19,9.4) 2(-15.19,5.64) 3(-15.19,1.88) 4(-15.19,-1.88) 5(-15.19,-5.64) 6(-15.19,-9.4) 7(15.19,-9.4) 8(15.19,-5.64) 9(15.19,-1.88) 10(15.19,1.88) 11(15.19,5.64) 12(15.19,9.4)
  silkscreen extent -14.12,-13.51 14.12,14, body extent -16.16,-13 16.15,13, height 13.08
XAL5030 [mil] "Coilcraft XAL5030 12/12/11"
  rect 46x183 smd: 1(-65,0) 2(65,0)
  silkscreen extent -108,-112 108,112, body extent -108,-112 108,112, height 122
XFL4020 [mm] "Coilcraft XFL4020 7/18/12"
  rect 0.98x3.4 smd: 1(-1.181,0) 2(1.181,0)
  silkscreen extent -2.16,-2.16 2.16,2.16, body extent -2.15,-2.15 2.15,2.15, height 2.1

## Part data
C1 C2 C3 C4: "CAP, CERM, 0.01uF, 100V, +/-10%, X7R, 0603"
C5: "CAP, CERM, 1000 pF, 2000 V, +/- 10%, X7R, 1808"
C6: "CAP, CERM, 1000 pF, 2000 V,+/- 10%, X7R, 1812"
C7 C8 C13 C14: "CAP, CERM, 1000pF, 100V, +/-10%, X7R, 0603"
C9 C10 C11 C12: "CAP, CERM, 330 pF, 50 V, +/- 5%, C0G/NP0, 0603"
C15: "CAP, CERM, 0.01uF, 50V, +/-10%, X7R, 0603"
C16: "CAP, CERM, 0.01 µF, 50 V, +/- 10%, X5R, 0603"
C17: "CAP, AL, 47 µF, 63 V, +/- 20%, 0.65 ohm, SMD"
C18: "CAP, CERM, 0.1 µF, 25 V, +/- 10%, X5R, 0603"
C19 C21 C26: "CAP, CERM, 0.1 µF, 100 V, +/- 10%, X7R, 0805"
C20 C36: library part CMP-0009295-2, "CAP, CERM, 4700 pF, 2000 V, +/- 10%, X7R, 1812"
C22 C23 C24 C25: "CAP, CERM, 2.2 µF, 100 V, +/- 10%, X7R, 1210"
C27: "CAP, Aluminum Polymer, 270 µF, 25 V,+/- 20%, 0.027 ohm, D10xL12.7mm SMD"
C28 C29 C30: "CAP, CERM, 10 µF, 25 V, +/- 10%, X7R, 1210"
C31 C40 C46: "CAP, CERM, 1 µF, 25 V, +/- 10%, X7R, 0805"
C32: "CAP, CERM, 100 pF, 250 V, +/- 5%, C0G/NP0, 0805"
C33: library part CMP-0006893-4, "CAP, CERM, 220 pF, 50 V, +/- 5%, C0G/NP0, 0603"
C34: "CAP, CERM, 0.022 µF, 25 V,+/- 10%, X7R, 0603"
C35 C44: "CAP, CERM, 100 pF, 50 V, +/- 5%, C0G/NP0, 0603"
C37: library part GRM188R72A332KA01D, "CAP, CERM, 3300 pF, 100 V, +/- 10%, X7R, 0603"
C38: library part CMP-0007216-4, "CAP, CERM, 3900 pF, 50 V, +/- 5%, C0G/NP0, 0603"
C39: library part CMP-0006752-5, "CAP, CERM, 0.1 uF, 25 V, +/- 5%, X7R, 0603"
C41: library part CMP-0007121-4, "CAP, CERM, 2.2 uF, 16 V, +/- 10%, X7R, 0603"
C43: library part CMP-0006757-5, "CAP, CERM, 0.047 uF, 25 V, +/- 5%, X7R, 0603"
C45: "CAP, CERM, 0.047 µF, 50 V, +/- 10%, X7R, 0603"
D1 D2 D3 D4: "Diode, Schottky, 100 V, 2 A, SMB"
D5: "Diode, TVS, Uni, 58V, 600W, SMB"
D6 D7 D8 D9: library part B2100-13-F, "Diode, Schottky, 100 V, 2 A, SMB"
D10: library part PDS5100-13, "Diode, Schottky, 100 V, 5 A, PowerDI5"
D11 D12 D13: library part 150060YS75000, "LED, Yellow, SMD"
D14: "Diode, Superfast Rectifier, 200 V, 2 A, SMA"
D15 D17: "Diode, Switching, 100 V, 0.2 A, SOD-123"
D16: "LED, Yellow, SMD"
D18: library part SBRT20U60SP5-7, "Diode, Super Barrier Rectifier, 60 V, 20 A, AEC-Q101, PowerDI5"
D19: library part CMP-0005802-3, "Diode, Zener, 5.1 V, 500 mW, SOD-123"
D21: "Diode, Schottky, 30 V, 0.2 A, SOT-23"
FID1 FID2 FID3 FID4 FID5 FID6: "Fiducial mark.  There is nothing to buy or mount."
H1 H2 H3 H4: "Bumpon, Hemisphere, 0.375 X 0.235, Black"
J1 J2: "RJ-45, No LED, tab up, R/A, TH"
J3: "Terminal Block, 3.5 mm, 2x1, Tin, TH"
J4 J5: "Header, 2.54 mm, 2x1, Gold, R/A, SMT"
J6: "Header, 100mil, 3x1, Gold, SMT"
J7: "Header, 100mil, 2x2, Tin, SMT"
J8: "Header, 2.54mm, 3x2, Gold, SMT"
J9 J10 J12: library part 87898-0204, "Header, 2.54 mm, 2x1, Gold, R/A, SMT"
J11: "Terminal Block, 3.5mm Pitch, 2x1, TH"
L1 L3 L4 L6: library part 742792641, "Ferrite Bead, 300 ohm @ 100 MHz, 2 A, 0603"
L2 L5: "Coupled inductor, 250 µH,  A, 0.035 ohm, SMD"
L7: "Inductor, Shielded, Composite, 3.3 µH, 2.9 A, 0.03 ohm, SMD"
L8: library part CMP-0061000-2, "Inductor, Shielded, Composite, 160 nH, 22.2 A, 0.00215 ohm, AEC-Q200 Grade 1, SMD"
Logo3: library part FCC_disclaimer, "FCC_disclaimer"
Q1 Q2 Q3 Q4: "MOSFET, N-CH, 100V, 2.7A, SSOT-3"
Q5: "MOSFET, N-CH, 150 V, 4.6 A, PQFN08A"
Q7: library part CMP-0000330-2, "Transistor, PNP, 20 V, 1.5 A, SOT-23"
R1 R2 R3 R4 R5 R6 R7 R8: "RES, 75.0 ohm, 1%, 0.1W, 0603"
R9 R10 R11 R12: "RES, 1.00 M, 1%, 0.1 W, 0603"
R13 R14 R15 R16: "RES, 232 k, 1%, 0.1 W, 0603"
R17: "RES, 237k ohm, 1%, 0.1W, 0603"
R18: "RES, 9.53 k, 1%, 0.1 W, 0603"
R19: library part CMP-0022532-4, "RES, 60.4 k, 1%, 0.1 W, AEC-Q200 Grade 0, 0603"
R20 R21 R22: "RES, 24.9 k, 1%, 0.1 W, 0603"
R23: "RES, 27.4 k, 1%, 0.1 W, 0603"
R24 R29: "RES, 63.4 ohm, 1%, 0.1W, 0603"
R25: "RES, 90.9, 1%, 0.1 W, 0603"
R26 R41 R63: "RES, 0, 5%, 0.1 W, 0603"
R27: "RES, 249, 1%, 0.1 W, 0603"
R28: "RES, 1.21 k, 1%, 0.1 W, 0603"
R30: "RES, 1.00 k, 1%, 0.75 W, 2010"
R31: "TRIMMER, 2k ohm, 0.5W, TH"
R32: "RES, 49.9 k, 1%, 0.1 W, 0603"
R33: "RES, 39 k, 5%, 0.25 W, 1206"
R34: library part CMP-0024655-3, "RES, 133 k, 0.5%, 0.1 W, 0603"
R35: library part CMP-0025703-4, "RES, 10, 5%, 0.1 W, AEC-Q200 Grade 0, 0603"
R36: "RES, 75, 5%, 0.75 W, AEC-Q200 Grade 0, 2010"
R37: "RES, 4.99 k, 0.5%, 0.1 W, 0603"
R38: "RES, 0.02, 1%, 1 W, 2010"
R39: "RES, 5.23, 1%, 0.125 W, 0805"
R40: library part CMP-0021990-4, "RES, 100 k, 1%, 0.1 W, AEC-Q200 Grade 0, 0603"
R42: library part CMP-0025330-3, "RES, 499, 0.5%, 0.1 W, 0603"
R43: library part CMP-0025543-3, "RES, 71.5 k, 0.5%, 0.1 W, 0603"
R44: "RES, 4.42 k, 1%, 0.1 W, 0603"
R45: library part CMP-0022279-4, "RES, 2.61 k, 1%, 0.1 W, AEC-Q200 Grade 0, 0603"
R46: library part CMP-0022274-4, "RES, 2.32 k, 1%, 0.1 W, AEC-Q200 Grade 0, 0603"
R47 R48: library part CRCW251215R0JNEG, "RES, 15, 5%, 1 W, AEC-Q200 Grade 0, 2512"
R53: "RES, 50, 1%, 0.1 W, 0603"
R54: library part CMP-0022270-4, "RES, 2.10 k, 1%, 0.1 W, AEC-Q200 Grade 0, 0603"
R55 R59: "RES, 10.0 k, 1%, 0.1 W, 0603"
R56: "RES, 4.99 k, 1%, 0.1 W, 0603"
R57: library part CMP-0022631-5, "RES, 887, 1%, 0.1 W, AEC-Q200 Grade 0, 0603"
R60: "RES, 14.7 k, 1%, 0.1 W, 0603"
R61: "RES, 2.61 k, 1%, 0.1 W, 0603"
R62: library part CMP-0021999-4, "RES, 10.2 k, 1%, 0.1 W, AEC-Q200 Grade 0, 0603"
"RoHS Exempt": library part EURoHS_Exempt
SH-J1 SH-J2 SH-J3 SH-J4 SH-J5 SH-J6 SH-J7 SH-J8: "Shunt, 100mil, Flash Gold, Black"
T1: "Transformer, 350 uH, SMT"
T2: library part CMP-0077631-2, "Transformer, 30 uH, SMT"
TP1 TP2 TP3 TP4 TP5 TP6 TP7 TP8 TP9 TP10 TP14 TP15 TP16 TP17 TP18 TP19 TP20 TP21 TP22 TP23 TP24 TP25 TP26 TP27: library part 5019, "Test Point, Miniature, SMT"
TP11 TP12 TP13: "Test Point, Miniature, SMT"
U1: library part CMP-0013754-2, "High-Power PoE PD Interface with Advanced Startup, RGW0020B (VQFN-20)"
U2: library part CMP-0081541-1, "Automotive Grade 2.2-MHz Wide Input Non-synchronous Boost Controller, DSS0012C (WSON-12)"
U3: "Optocoupler, 5 kV, 80-160% CTR, SMT"
U4: library part CMP-0084729-1, "Programmable Shunt Regulator with Optimized Reference Current, DBZ0003A (SOT-23-3)"
ZZ1 ZZ2 ZZ3: library part AssemblyNote

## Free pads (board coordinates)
  rrect40% 19.68x9.84 smd far side: 2(3302.6,2150.47) 3(3302.6,2170.16) 4(3302.6,2189.84) 7(3377.4,2229.21) 8(3377.4,2209.53) 9(3377.4,2189.84) 10(3377.4,2170.16) 11(3377.4,2150.47) 12(3377.4,2130.79)

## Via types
v1: diameter 30, hole 10, Top Layer to Bottom Layer, 128 vias
v2: diameter 50, hole 28, Top Layer to Bottom Layer, 77 vias
v3: diameter 40, hole 20, Top Layer to Bottom Layer, 21 vias
v4: diameter 19.68, hole 7.87, Top Layer to Bottom Layer, 8 vias
v5: diameter 20, hole 8, Top Layer to Bottom Layer, 4 vias
v6: diameter 50, hole 20, Top Layer to Bottom Layer, 2 vias

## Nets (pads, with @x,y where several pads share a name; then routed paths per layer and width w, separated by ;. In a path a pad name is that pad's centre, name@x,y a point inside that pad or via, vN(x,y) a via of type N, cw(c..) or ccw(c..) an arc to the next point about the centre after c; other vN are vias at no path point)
APD: C15.2 J4.2 R18.2 U1.10 | length 550.3
  Top Layer w10: U1.10@4181.54,1321.18 4239.25,1321.18 4268.94,1350.87 J4.2@4370,1350.87
  Top Layer w20: J4.2@4360,1360.87 4360,1430 4375,1445 v1(4420,1445)
  Bottom Layer w20: R18.2@4240,1362.44 4337.44,1362.44 v1(4420,1445)
BT: D13.1 TP13.1 U1.19 | length 2748.8
  Top Layer w10: v1(3900,1140) 3930,1170 3930,1210 3964.41,1244.41 U1.19@3998.46,1244.41
  Top Layer w20: v1(5220,2615) 5317.82,2615 5317.82,2701.14 5281.3,2737.65 D13.1@5281.3,2799.98
  MidLayer2 w20: v1@3905,1140 3930.62,1165.62 3930.62,1286.37 3910,1306.99 3910,1730 4730,2550 5155,2550 v1(5220,2615)
EARTH: C5.2 C6.2 J1.9 J1.10 J1.11 J1.12 J2.9 J2.10 J2.11 J2.12 TP5.1 | length 1099.1
  Bottom Layer w50: J2.11@203,2588.25 269,2522.25 339,2522.25 446.75,2630 446.75,3051.68 J2.10@337.95,3160.47 J2.12@268.98,3091.5 ; 459.69,3038.74 C6.2@570,3038.74
  other v1: 1630,90 510,110 2450,140 860,660 1140,1410 1810,1410 2470,1410 78.19,1551.89 93.15,1970
  other v2: 100,2930
GND: C20.1 C27.2 C28.2 C29.2 C30.2 C31.2 C36.1 C46.2 D18.1 D18.2 J11.2 R44.1 R47.1 R48.1 R61.1 TP22.1 U4.3 | length 110.2
  Top Layer w50: v2(1490,2150) 1490,2040.47 C46.2@1490.47,2040
  other v1: 930,1620 1370,1620 2070,1620 2660,1850 930,2090 2760,2100 2230,2110 2030,2160 2760,2450 930,2560 2750,2820 920,3100 2760,3170 2090,3280 2760,3480
  other v2: 1650,2440 1580,2510 1650,2510 1580,2580 1650,2580 1580,2650 1650,2650 1580,2720 1650,2720 1580,2790 1650,2790 1580,2860 1650,2860
MPS_DUTY: J6.2 TP6.1 U1.9 | length 1875.7
  Top Layer w10: U1.9@4181.54,1295.59 4275.59,1295.59 v1(4295,1315) ; v1(4655,155) TP6.1@4775,155
  Top Layer w50: TP6.1@4780,160 5047.5,160 J6.2@5070,182.5
  MidLayer1 w10: v1@4302.87,1307.13 v1(4295,1315) 4320,1315 4380,1255 4380,550 4655,275 v1(4655,155)
NetC1_2: C1.2 R1.2 | length 77
  Bottom Layer w30: C1.2@733.15,1642.99 R1.2@733.15,1720
NetC2_2: C2.2 R2.2 | length 77
  Bottom Layer w30: C2.2@583.15,1642.99 R2.2@583.15,1720
NetC3_2: C3.2 R3.2 | length 77
  Bottom Layer w30: C3.2@433.15,1642.99 R3.2@433.15,1720
NetC4_2: C4.2 R4.2 | length 77
  Bottom Layer w30: C4.2@283.15,1642.99 R4.2@283.15,1720
NetC5_1: C5.1 R1.1 R2.1 R3.1 R4.1 | length 603.5
  Bottom Layer w40: C5.1@143.15,1815.59 175.75,1782.99 R4.1@283.15,1782.99 R3.1@433.15,1782.99 R2.1@583.15,1782.99 R1.1@733.15,1782.99
NetC6_1: C6.1 R5.2 R6.2 R7.2 R8.2
NetC7_1: C7.1 D1.1 D2.1 D3.1 D4.1 L2.2 | length 1938.9
  Top Layer w50: C7.1@2600,981.5 2600,1050
  Top Layer w80: D4.1@1060,1227.01 D3.1@1450,1227.01 D2.1@1820,1227.01 D1.1@2210,1227.01 2407.99,1227.01 v3(2560,1075)
  Top Layer w100: v3@2562.56,1072.44 L2.2@2870,1072.44
NetC7_2: C7.2 C9.2 C10.2 C11.2 C12.2 D6.2 D7.2 D8.2 D9.2 L2.3 Q1.2 Q2.2 Q3.2 Q4.2 R13.1 R14.1 R15.1 R16.1 | length 2248.3
  Top Layer w50: R16.1@1101.5,690 v2(1180,690) ; 1480,690 v2(1570,690) ; R14.1@1861.5,690 v2(1940,690) ; R13.1@2251.5,690 v2(2330,690) ; 2600,860 C7.2@2600,918.5
  Top Layer w100: v3@2562.44,827.56 L2.3@2870,827.56
  Bottom Layer w80: D9.2@1060,692.99 D8.2@1450,692.99 D7.2@1820,692.99 D6.2@2210,692.99 2422.99,692.99 v3(2560,830)
NetC9_1: C9.1 Q1.1 R9.1 R13.2 | length 110.8
  Top Layer w30: R9.1@2071.5,840 2149.29,840 Q1.1@2172.6,816.69
NetC10_1: C10.1 Q2.1 R10.1 R14.2 | length 440.9
  Top Layer w30: v2(1940,910) R10.1@2008.5,910
  Top Layer w50: v2(1690,820) Q2.1@1769.29,820
  MidLayer1 w30: v2(1690,820) 1690,830 1770,910 v2(1940,910)
NetC11_1: C11.1 Q3.1 R11.1 R15.2 | length 114.9
  Top Layer w30: R11.1@1311.5,840 1379.29,840 Q3.1@1412.6,806.69
NetC12_1: C12.1 Q4.1 R12.1 R16.2 | length 429.3
  Top Layer w10: Q4.1@1022.6,816.69 Q4.1@1028.5,810.79
  Top Layer w30: v2(1180,910) R12.1@1248.5,910
  Top Layer w50: v2(940,820) Q4.1@1009.29,820
  MidLayer1 w30: v2(940,820) 940,830 1020,910 v2(1180,910)
NetC13_1: C13.1 D10.1 D10.2 L4.2 R17.2 | length 697.4
  MidLayer1 w30: v1(4470,1450) 4790,1770 v1(4790,1900)
  Bottom Layer w30: R17.2@4470,1407.56 v1(4470,1450)
  Bottom Layer w50: C13.1@4730,1907.56 4730,1980
NetC14_1: C14.1 J3.2 L5.2
NetC14_2: C14.2 J3.1 L5.3
NetC20_2: C20.2 C23.1 C24.1 C25.1 C26.2 L7.2 R33.2 T2.1 T2.2
  other v1: 3580,2510 3580,2550 3580,2590 3580,2630 3580,2670 3580,2710
NetC26_1: C26.1 D14.1 R33.1
NetC27_1: C27.1 C31.1 J11.1 J12.1 L8.2 R53.2 TP19.1 | length 702.3
  Top Layer w10: TP19.1@1560,3370 TP19.1@1590,3400 ; J12.1@1730,3400 1740,3410 J12.1@1740,3440.87
  Top Layer w30: R53.2@1420,2610 R53.2@1420,2611.5 1420,3000 1480,3060 ; TP19.1@1590,3400 J12.1@1730,3400
  other v1: 1420,3060 1420,3160 1420,3250 1420,3340
NetC28_1: C28.1 C29.1 C30.1 L8.1 T2.8 T2.9
  other v2: 1740,3070 1810,3070 1880,3070 1950,3070 2020,3070 2090,3070 2160,3070 1740,3140 1810,3140 1880,3140 1950,3140 2020,3140 2090,3140 2160,3140
NetC32_1: C32.1 D14.2 Q5.5 Q5.6 Q5.7 Q5.8 T2.3 T2.4 TP20.1 | length 1324.3
  Top Layer w10: v2(4620,3250) TP20.1@4620,3410
  MidLayer1 w10: v2(3580,2950) 3610,2980 4350,2980 v2(4620,3250)
  other v2: 3580,2830 3580,2890 3580,3010
NetC32_2: C32.2 R36.2
NetC34_1: C34.1 pad.9 Q7.1 U2.9 | length 1083.6
  Top Layer w10: v1@3000.46,1940.46 Q7.1@3049.29,1940.46
  MidLayer1 w10: v1(3000,1940) 3000,2140 3200,2340 3410,2340 v1(3450,2300)
  Bottom Layer w10: U2.9@3377.4,2189.84 3408.35,2189.84 3412.13,2193.62 3463.62,2193.62 3480,2210 3480,2261.5 C34.1@3518.5,2300 v1(3450,2300)
NetC35_1: C35.1 R41.2 R42.1 | length 149.4
  Bottom Layer w20: C35.1@3167.56,2290 3168.5,2290.94 R42.1@3168.5,2370 ; R41.2@3168.5,2220 C35.1@3168.5,2289.06
NetC37_1: C37.1 D18.3 T2.11 T2.12
  other v2: 2120,2520 2180,2520 2120,2580 2180,2580 2120,2640 2180,2640 2120,2700 2180,2700
NetC37_2: C37.2 R47.2 R48.2
NetC38_1: C38.1 Q7.2 R46.1 R57.2 R62.1 TP24.1 U2.6 U3.4 | length 1262.6
  Top Layer w20: C38.1@3031.59,1830.85 U3.4@3031.59,1760 R57.2@3138.5,1760 3138.5,1853.94 R62.1@3132.44,1860 3124.09,1868.35 Q7.2@3124.09,1940.46 3124.09,1944.24 3010,2058.33 TP24.1@3010,2210 3010,2280 3020,2290 v1(3300,2290) ; 3080,1765.05 v1(3080,1860)
  Bottom Layer w10: v1(3300,2290) 3302.6,2287.4 U2.6@3302.6,2229.21
  Bottom Layer w20: R46.1@3078.5,1800 3080,1801.5 v1(3080,1860)
NetC41_1: C41.1 D19.1 R45.1 R46.2 | length 264.8
  Bottom Layer w20: C41.1@3141.5,1722.99 R46.2@3141.5,1800 ; R45.1@3148.5,1880 3148.5,1807.01 R46.2@3141.5,1800 ; D19.1@3240,1784.47 3224.47,1800 R46.2@3141.5,1800
NetC43_1: C43.1 R57.1 | length 90
  Top Layer w20: C43.1@3201.5,1670 R57.1@3201.5,1760
NetC44_1: C44.1 C45.1 R59.1 R61.2 U4.2
NetC44_2: C44.2 D21.1 R56.1 R60.1 U3.2 U4.1 | length 1240.6
  Top Layer w30: D21.1@1667.24,1902.6 1694.65,1930 v2(1770,1930) v2@1790,1930 ; R56.1@1802.6,1995.04 U4.1@1802.6,2048.82
  Top Layer w50: v2(1770,1930) 1800,1960 ; v2(2400,1660) U3.2@2668.41,1660
  Bottom Layer w50: v2(1770,1930) 2130,1930 v2(2400,1660)
NetC45_2: C45.2 R60.2 | length 90
  Top Layer w30: R60.2@1840,1862.44 C45.2@1930,1862.44
NetC46_1: C46.1 D21.3 R55.1
NetD11_2: D11.2 R20.1 | length 120.6
  Top Layer w20: D11.2@4914.3,2799.98 v1(4955,2800)
  Bottom Layer w20: R20.1@4882.8,2781.48 4901.32,2800 v1(4955,2800)
NetD12_2: D12.2 R21.1 | length 107.8
  Top Layer w20: D12.2@5130.85,2799.98 v1(5175,2800)
  Bottom Layer w20: R21.1@5111.32,2800 v1(5175,2800)
NetD13_2: D13.2 R22.1 | length 124.4
  Top Layer w20: D13.2@5344.3,2799.98 v1(5395,2800)
  Bottom Layer w20: R22.1@5321.32,2800 v1(5395,2800)
NetD15_1: D15.1 pad.3 R35.1 U2.3 | length 2253.8
  MidLayer1 w30: v1(3060,2080) 3130,2010 3680,2010 v1(3880,2210)
  Bottom Layer w10: v1(3060,2080) 3150.16,2170.16 U2.3@3302.6,2170.16
  Bottom Layer w30: v1(3880,2210) 4130,2460 R35.1@4130,3148.5
NetD15_2: D15.2 Q5.4 R35.2 TP21.1 | length 656.4
  Top Layer w30: v2(4330,3250) TP21.1@4330,3410
  Bottom Layer w20: v2@3930,3100 3980,3150 R35.2@4068.5,3150
  Bottom Layer w30: R35.2@4068.5,3150 4068.5,3208.5 4110,3250 v2(4330,3250)
  other v2: 3920,3030 3920,3100
NetD16_1: D16.1 R44.2 | length 80
  Top Layer w30: D16.1@2010,3411.5 R44.2@2090,3411.5
NetD16_2: D16.2 J12.2 | length 139.3
  Top Layer w30: J12.2@1840,3311.5 D16.2@1938.5,3410
NetD17_2: D17.2 R39.1
NetD21_2: D21.2 R53.1 R54.2 R55.2 R56.2 R59.2 TP27.1 | length 954.5
  Top Layer w30: R53.1@1420,2548.5 1420,2490 1700,2210 1700,2010
  Bottom Layer w50: v2(1720,2040) v2(2020,2040)
NetJ1_1: J1.1 T1.23 | length 1112
  Top Layer w20: J1.1@302.91,569.84 302.91,564.57 391.81,564.57 615,787.76 T1.23@615,1489.96
NetJ1_2: J1.2 T1.22 | length 959.5
  Top Layer w20: J1.2@372.99,610 565,802.01 T1.22@565,1489.96
NetJ1_3: J1.3 T1.20 | length 1269.8
  Top Layer w20: T1.20@465,1489.96 465,1195 v3(500,1160)
  MidLayer1 w20: J1.3@302.91,650.16 251.26,598.5 251.26,557.24 284.09,524.41 321.73,524.41 361.89,564.57 391.81,564.57 450,622.76 450,1110 v3(500,1160)
NetJ1_4: J1.4 T1.17 | length 870.9
  Top Layer w20: T1.17@315,1489.96 315,1195 430,1080 430,747.32 J1.4@372.99,690.32
NetJ1_5: J1.5 T1.16 | length 899.5
  Top Layer w20: T1.16@265,1489.96 265,1191.44 400,1056.44 400,980 250,830 250,783.39 J1.5@302.91,730.47
NetJ1_6: J1.6 T1.19 | length 753.9
  Top Layer w20: T1.19@415,1489.96 415,1185 v3(440,1160)
  MidLayer1 w20: J1.6@372.99,770.63 420,817.64 420,1136.44 v3@440,1156.44
NetJ1_7: J1.7 T1.14 | length 1031.9
  Top Layer w20: T1.14@165,1489.96 165,1195 v3(200,1160)
  MidLayer2 w20: v3(200,1160) 160,1200 120,1200 62.13,1142.13 62.13,918.45 169.79,810.79 J1.7@302.91,810.79
NetJ1_8: J1.8 T1.13 | length 909.9
  Top Layer w20: T1.13@115,1489.96 115,1185 v3(140,1160)
  MidLayer2 w20: v3(140,1160) 90,1110 90,930 163.78,856.22 372.99,856.22 J1.8@372.99,850.94
NetJ2_1: J2.1 T1.2 | length 769.1
  Top Layer w20: J2.1@302.91,2699.84 340,2662.76 340,2610.58 615,2335.58 T1.2@615,2060.04
NetJ2_2: J2.2 T1.3 | length 1089.4
  Top Layer w10: 700,2300 703.15,2296.85
  Top Layer w20: J2.2@372.99,2740 372.99,2627.01 700,2300 ; T1.3@568.15,2051.89 568.15,1991.85 583.15,1976.85 683.15,1976.85 703.15,1996.85 703.15,2296.85
NetJ2_3: J2.3 T1.5 | length 1064
  Top Layer w20: T1.5@468.15,2051.89 463.15,2056.89 470,2063.74 v3(470,2140)
  MidLayer1 w20: J2.3@302.91,2780.16 302.76,2780 250,2780 110,2640 110,2540 188.9,2461.1 310,2461.1 470,2301.1 v3(470,2140)
NetJ2_4: J2.4 T1.8 | length 832.7
  Top Layer w20: T1.8@320,2065.04 v3(320,2140)
  MidLayer2 w20: v3(320,2140) 320,2150 440,2270 440,2753.31 J2.4@372.99,2820.31
NetJ2_5: J2.5 T1.9 | length 964.3
  Top Layer w20: v3(260,2140) 260,2060.04 T1.9@268.15,2051.89
  MidLayer2 w20: v3(260,2140) 260,2150 410,2300 410,2530 397.17,2542.83 397.17,2544.84 362.48,2579.53 360.47,2579.53 285.59,2654.41 284.09,2654.41 257.48,2681.02 257.48,2682.52 250,2690 250,2807.56 J2.5@302.91,2860.47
